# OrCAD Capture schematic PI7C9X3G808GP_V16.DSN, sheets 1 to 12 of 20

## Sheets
1 07_3V3_to_1V8&0.95V_LDO: size A; title: PI7C9X3G808GP reference circuit; rev: 1.6; note: 07_3V3_to_1V8&0.95V_LDO
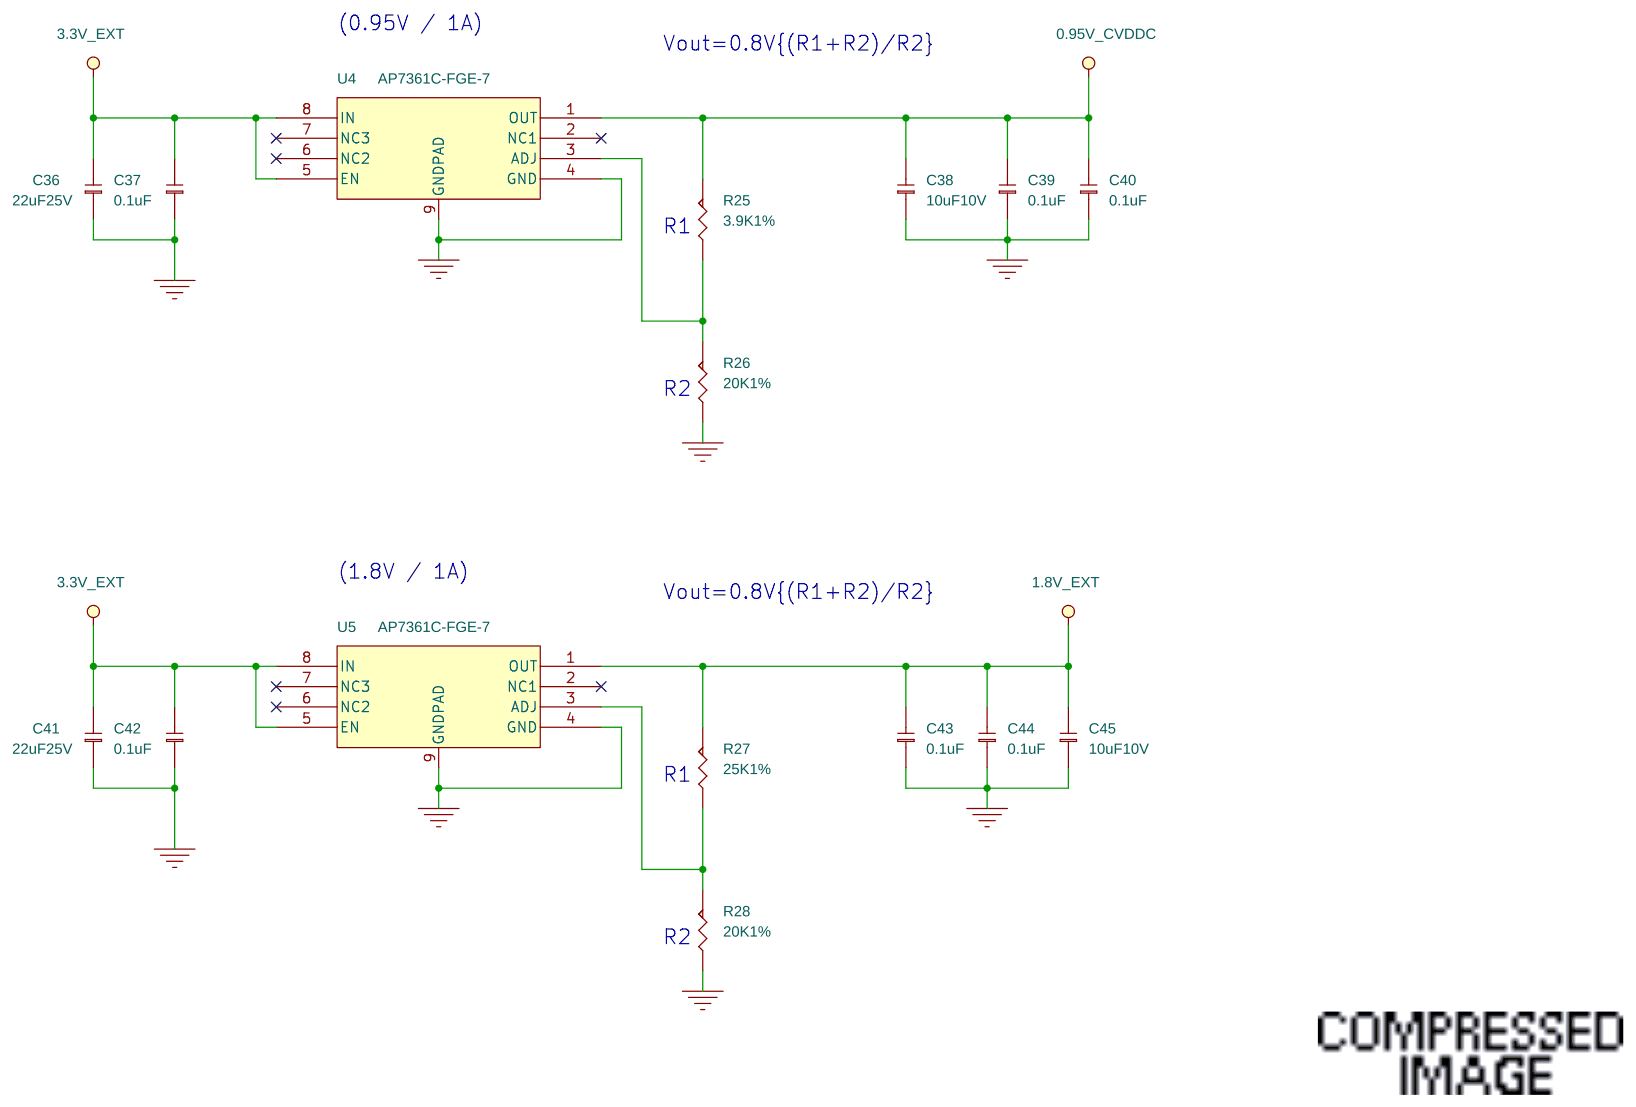
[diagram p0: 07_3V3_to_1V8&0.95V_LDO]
2 01_COVER SHEET: note: 01_COVER SHEET
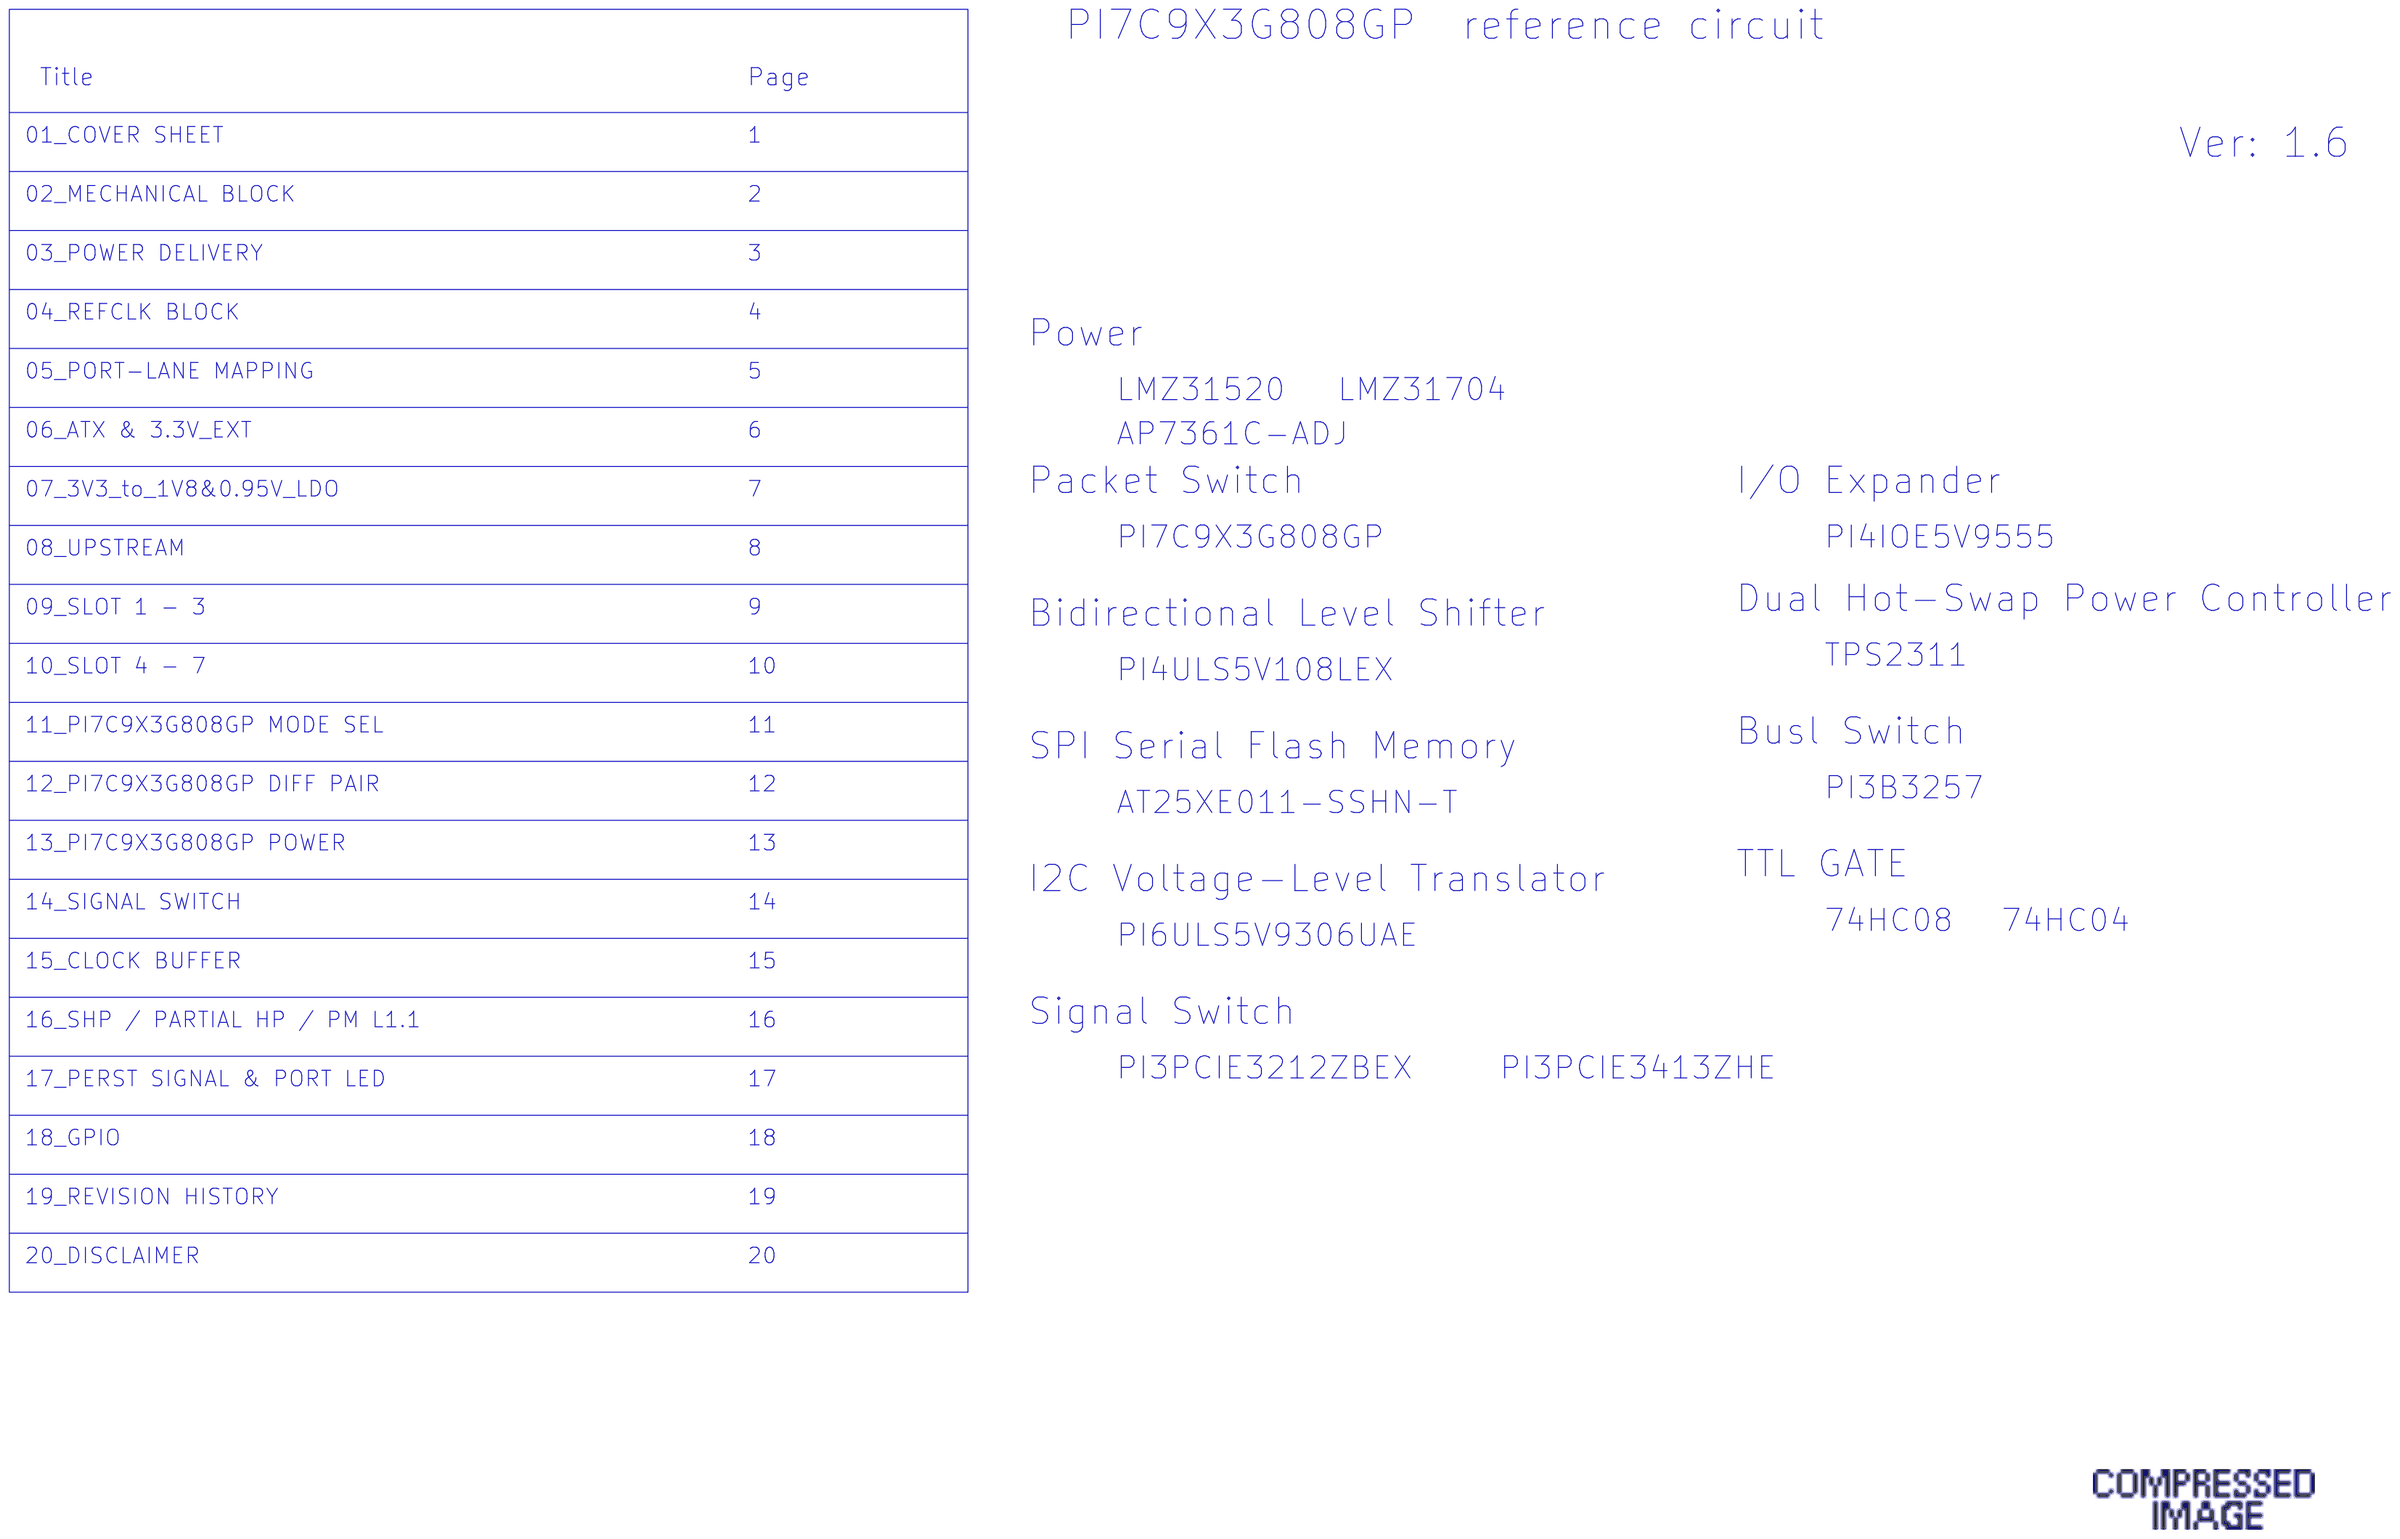
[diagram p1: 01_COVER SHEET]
3 02_MECHANICAL BLOCK: note: 02_MECHANICAL BLOCK
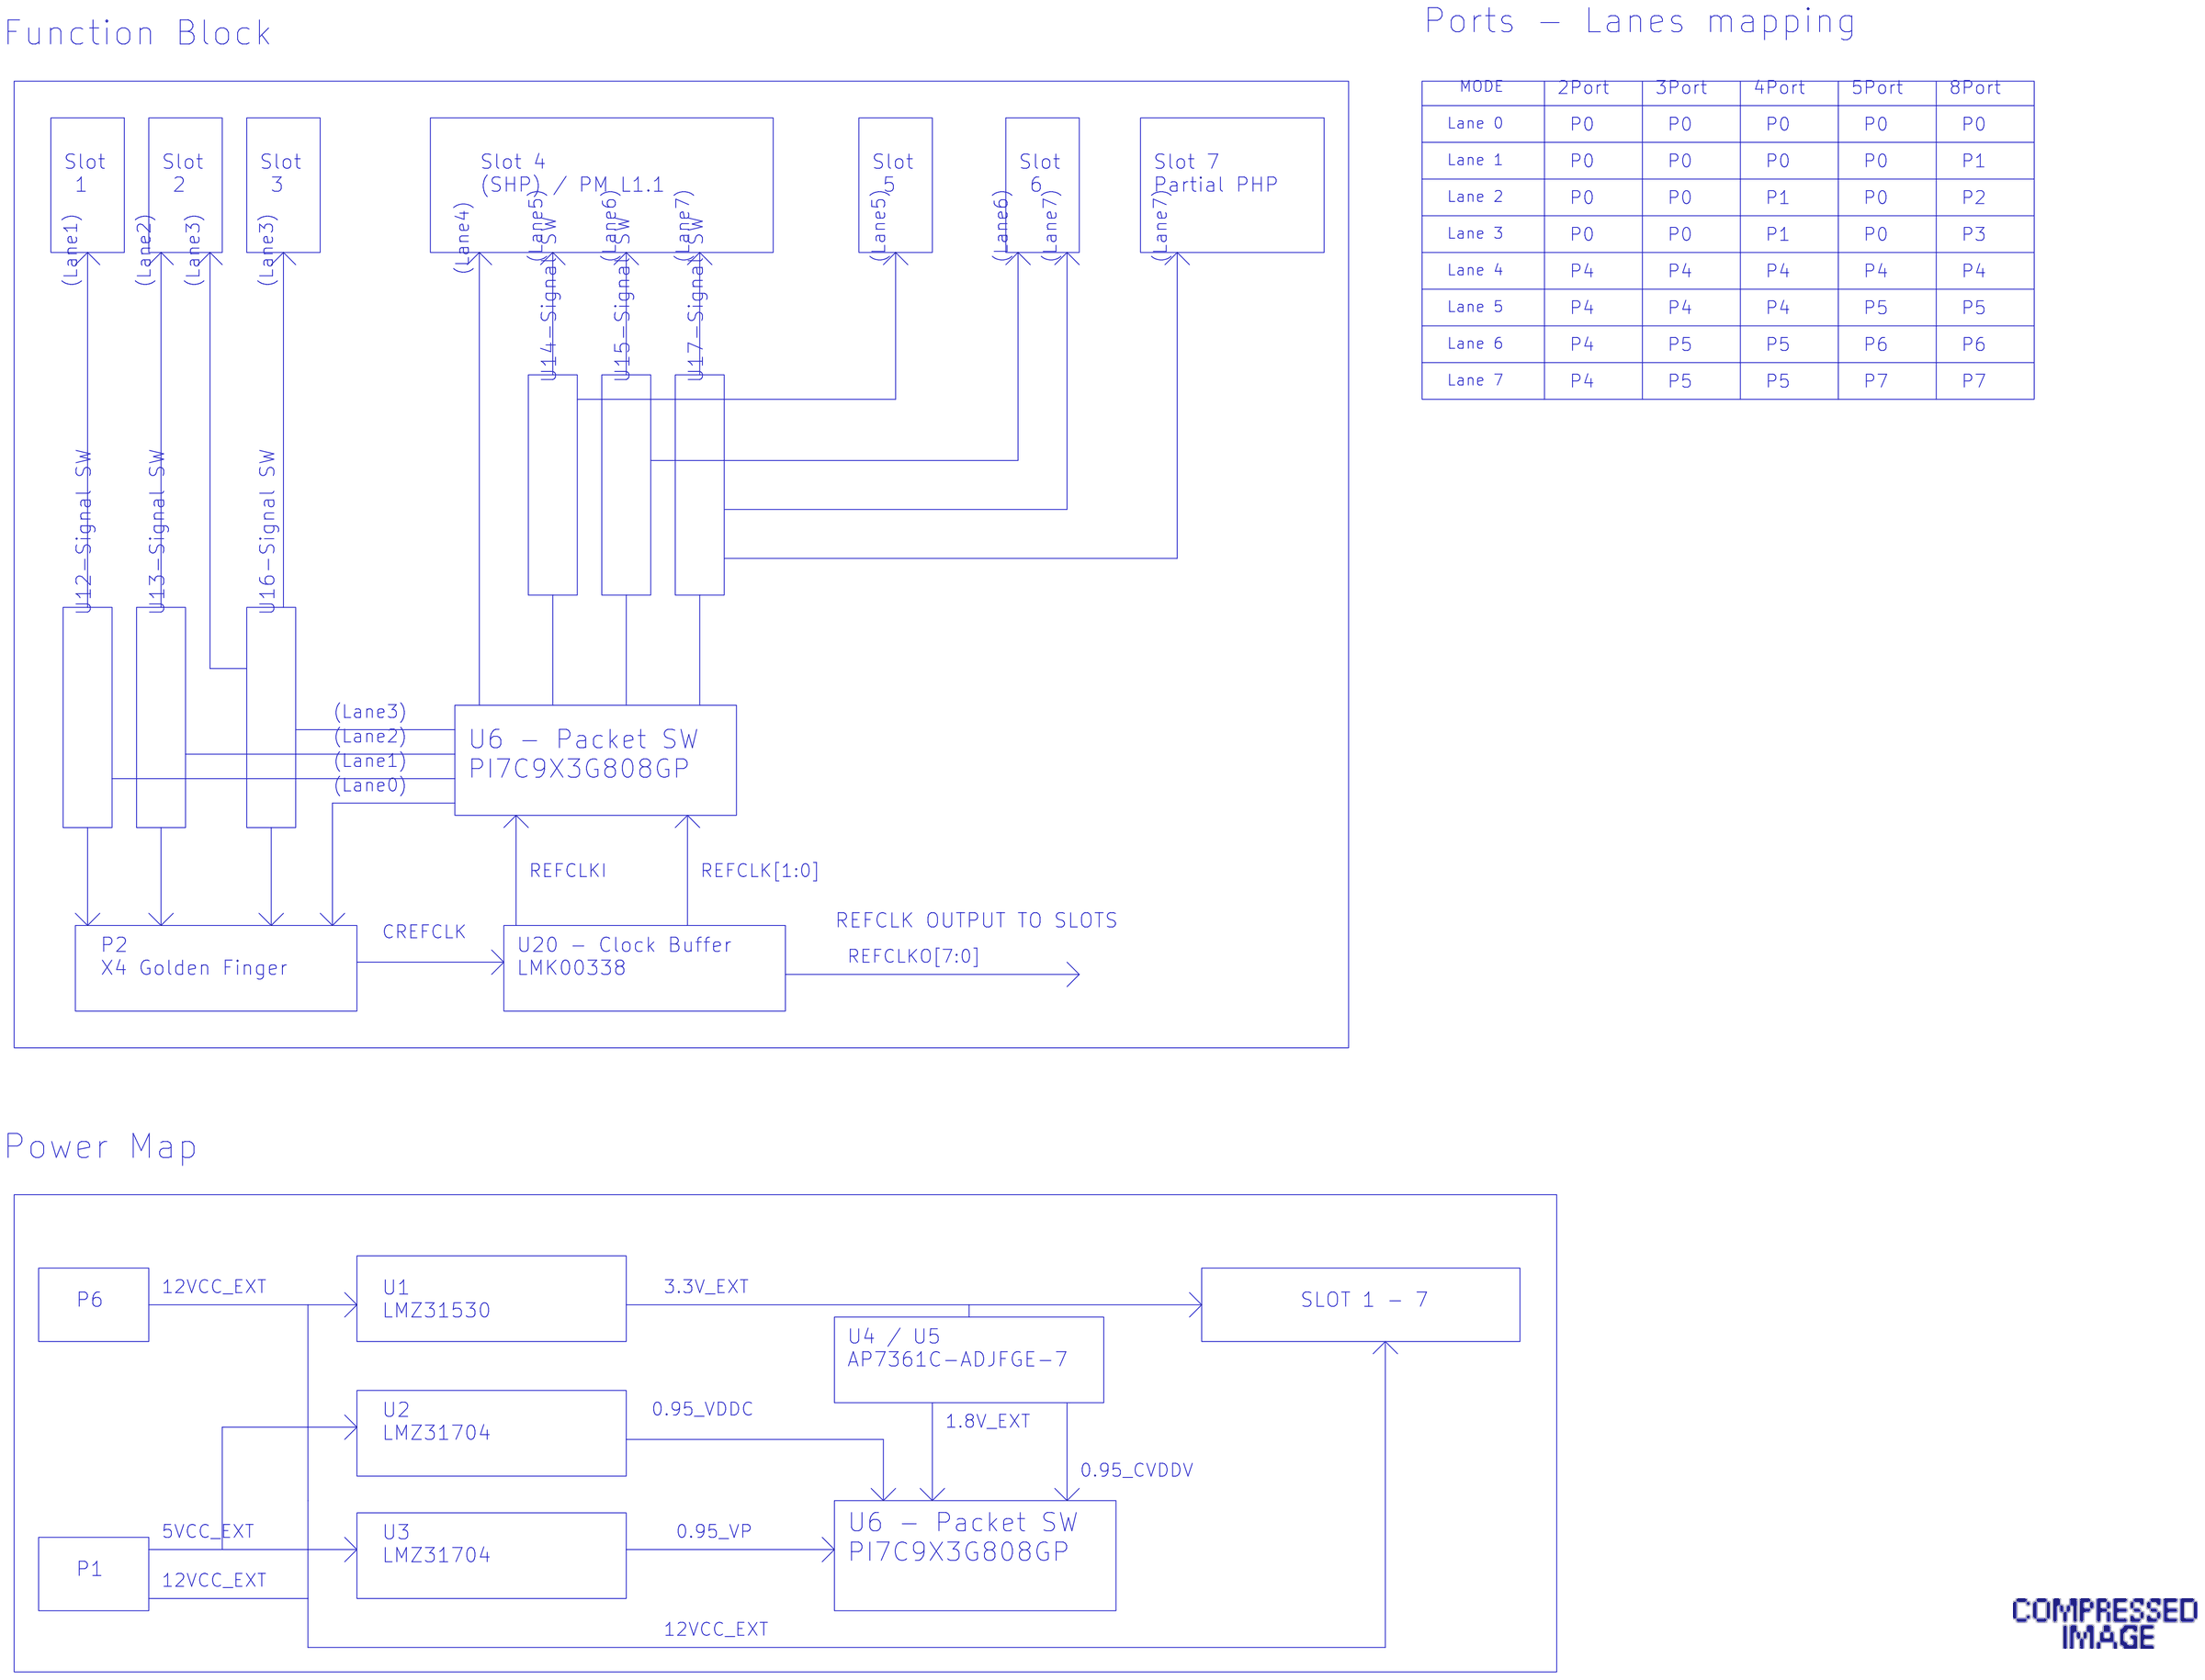
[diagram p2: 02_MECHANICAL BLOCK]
4 03_POWER DELIVERY: note: 03_POWER DELIVERY
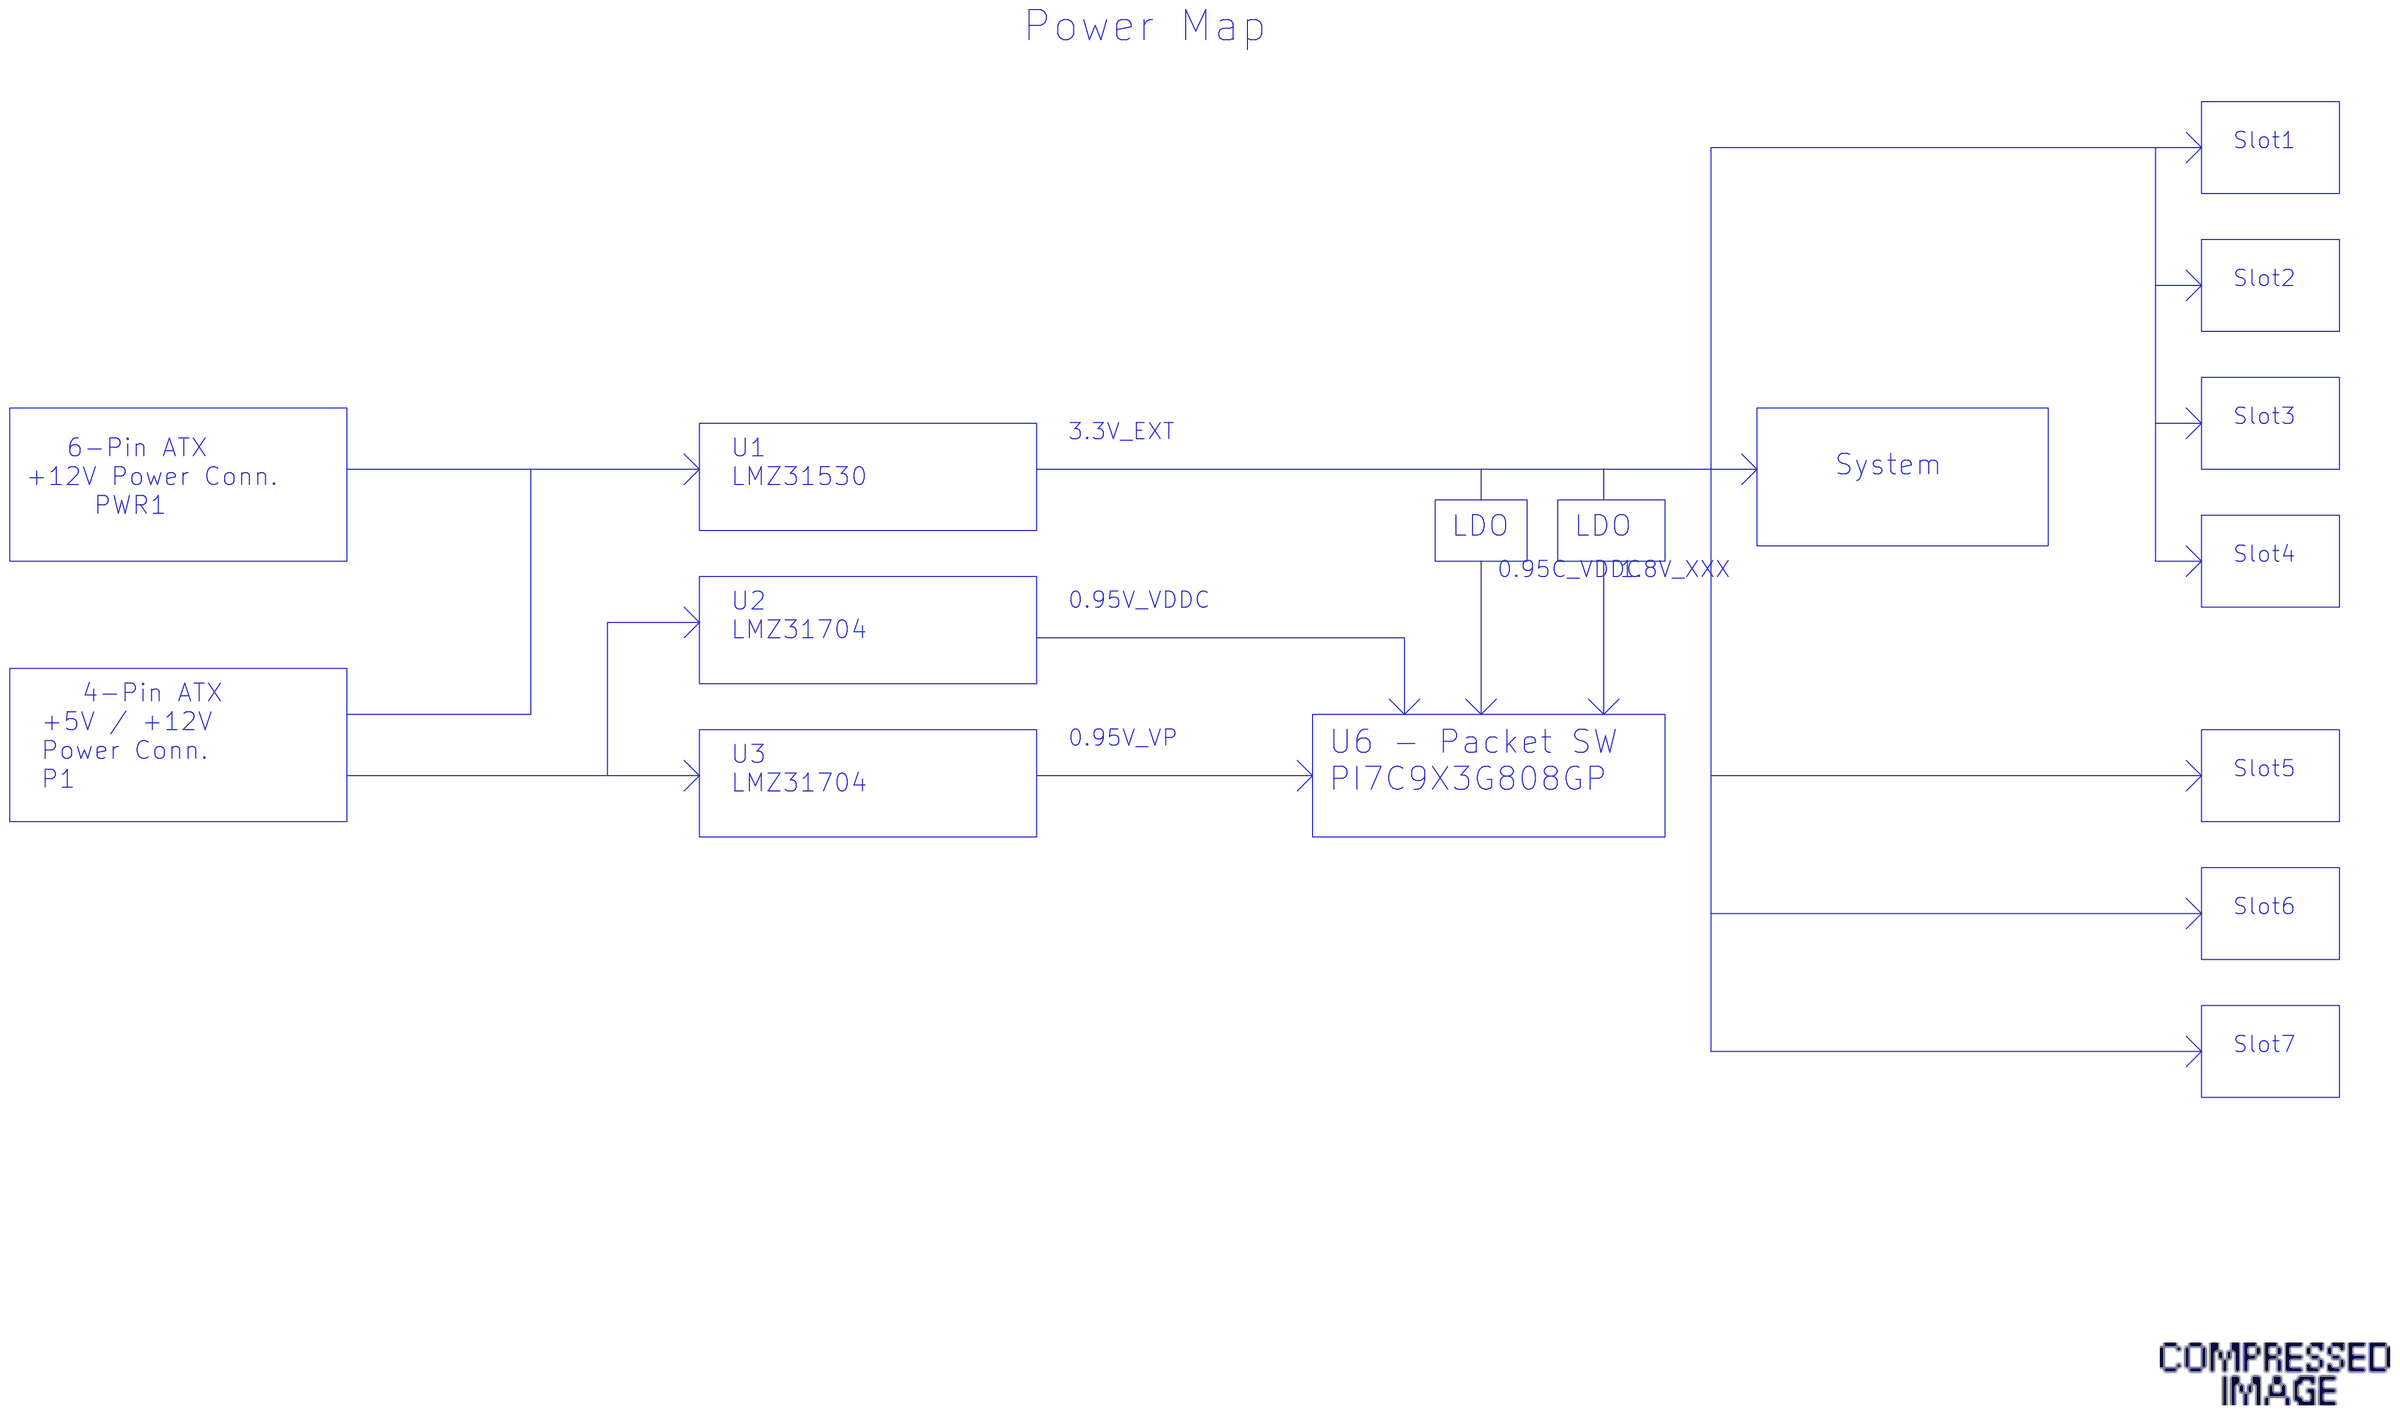
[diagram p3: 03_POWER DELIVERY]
5 04_REFCLK BLOCK: title: PI7C9X3G808GPA reference circuit; note: 04_REFCLK BLOCK
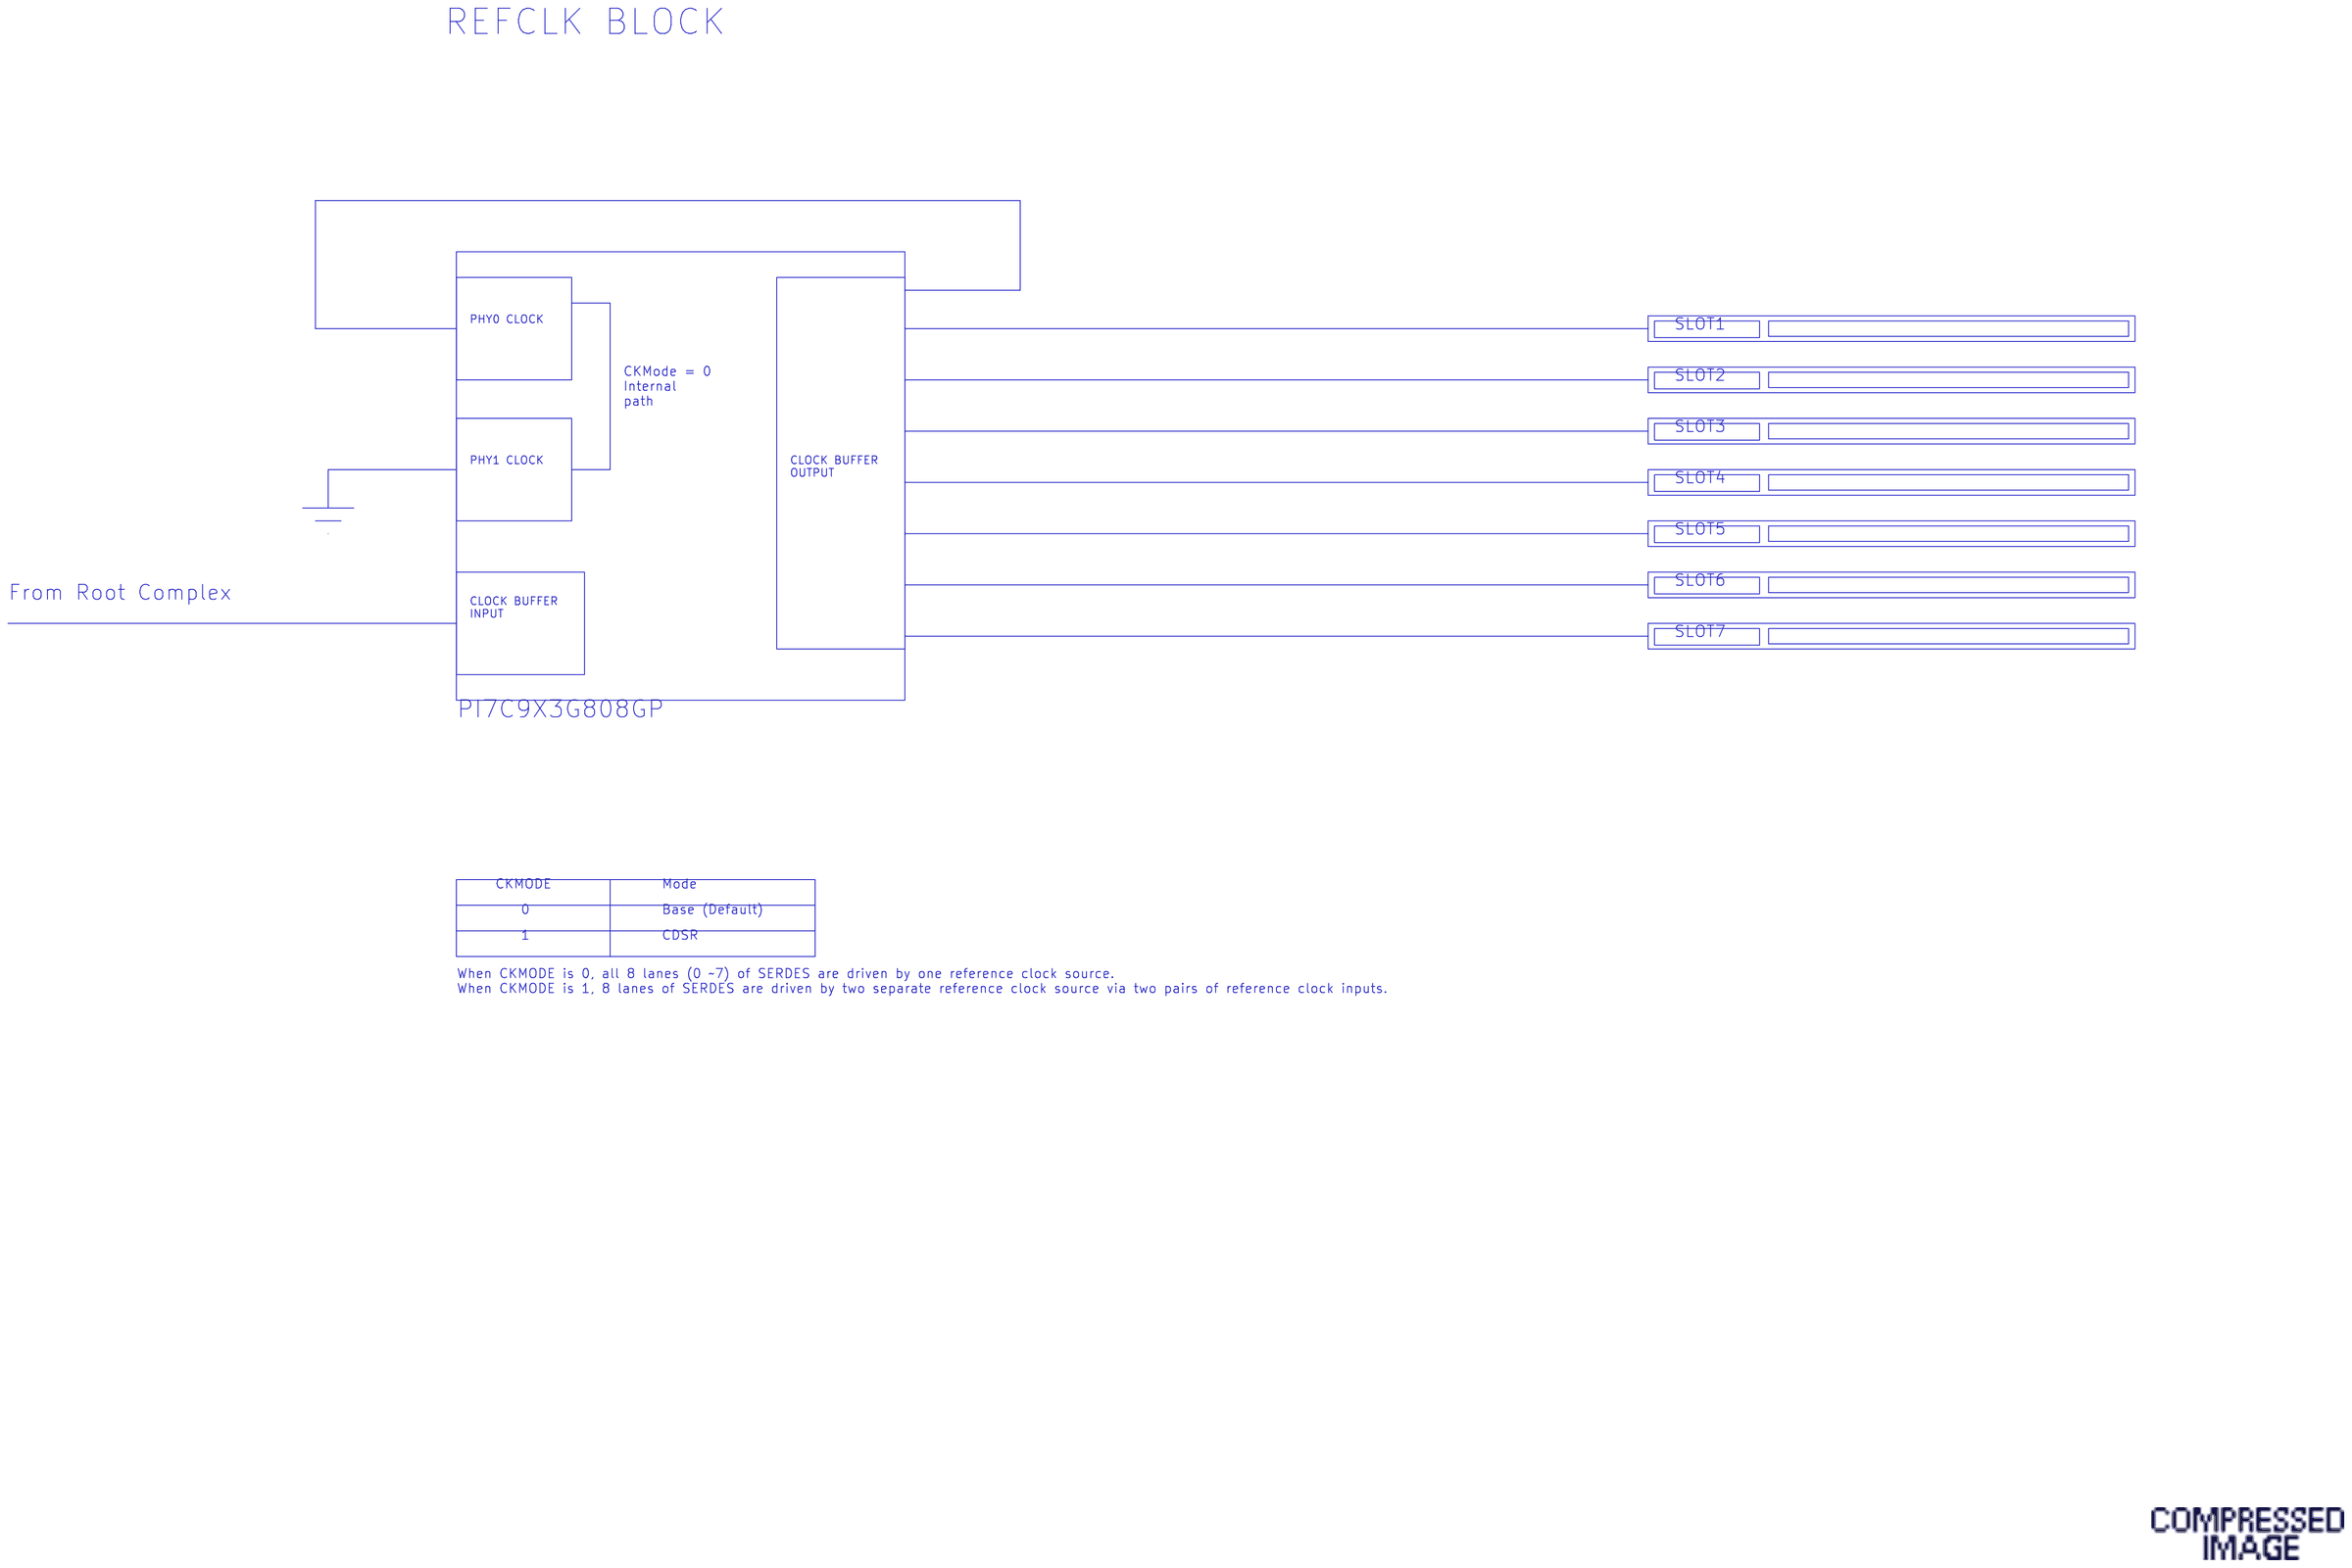
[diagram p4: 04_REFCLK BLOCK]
6 05_PORT-LANE MAPPING: note: 05_PORT-LANE MAPPING
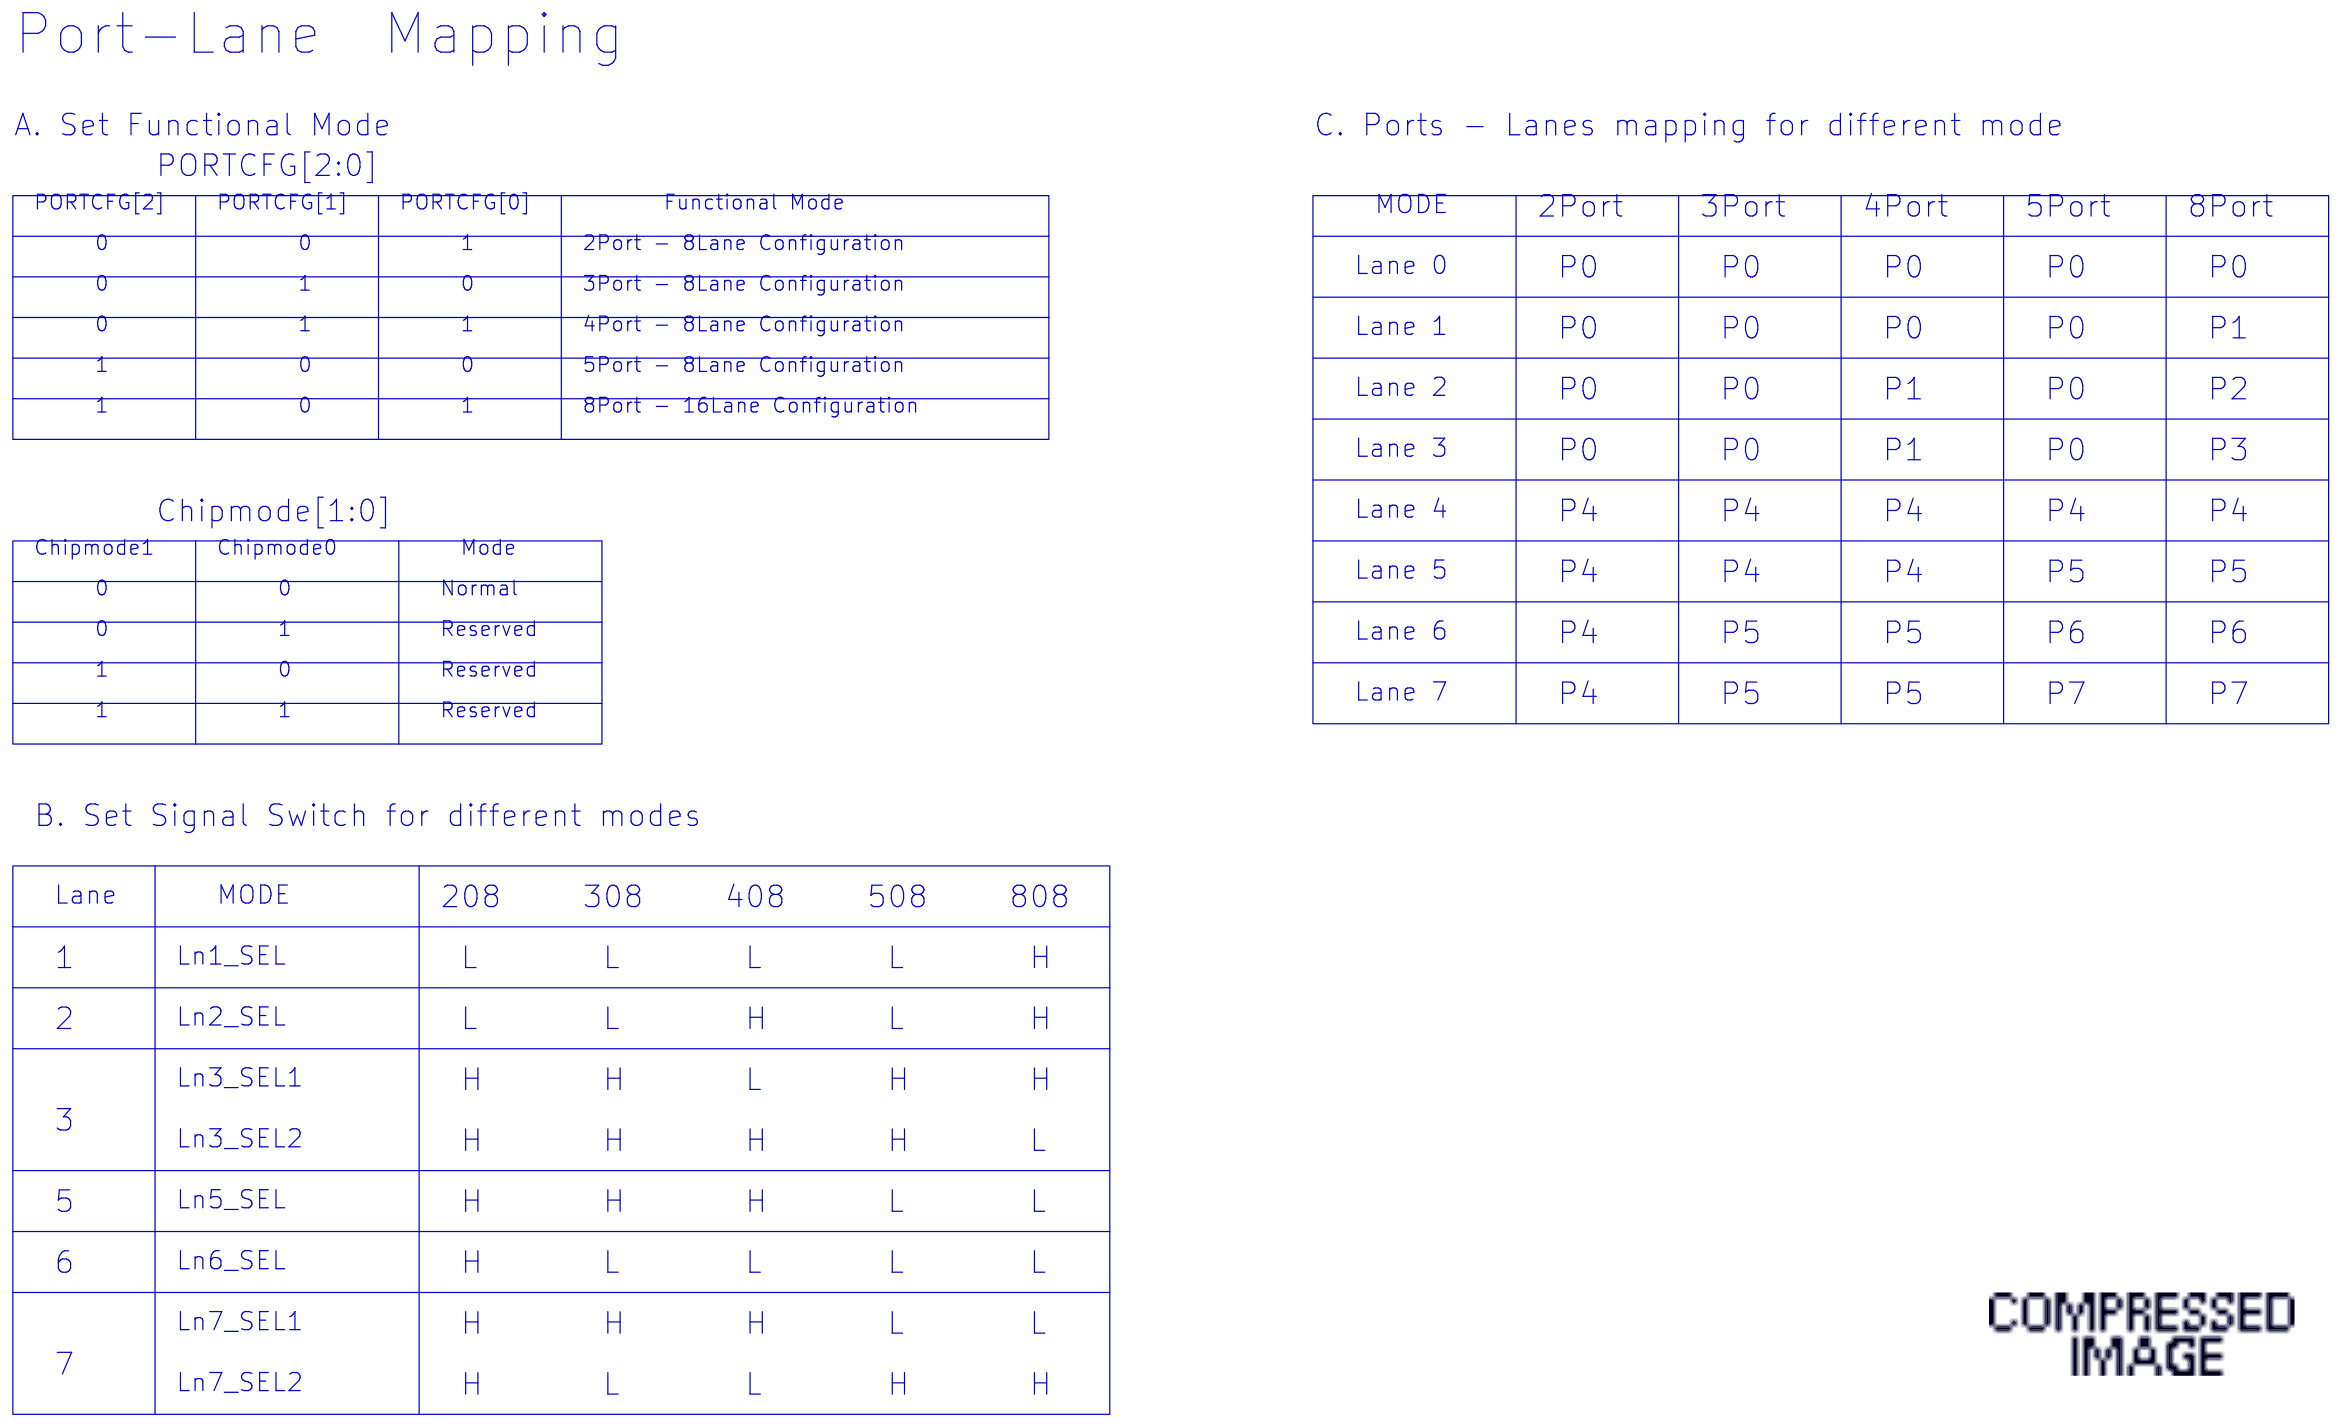
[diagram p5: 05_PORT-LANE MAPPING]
7 08_UPSTREAM: size Custom; note: 08_UPSTREAM
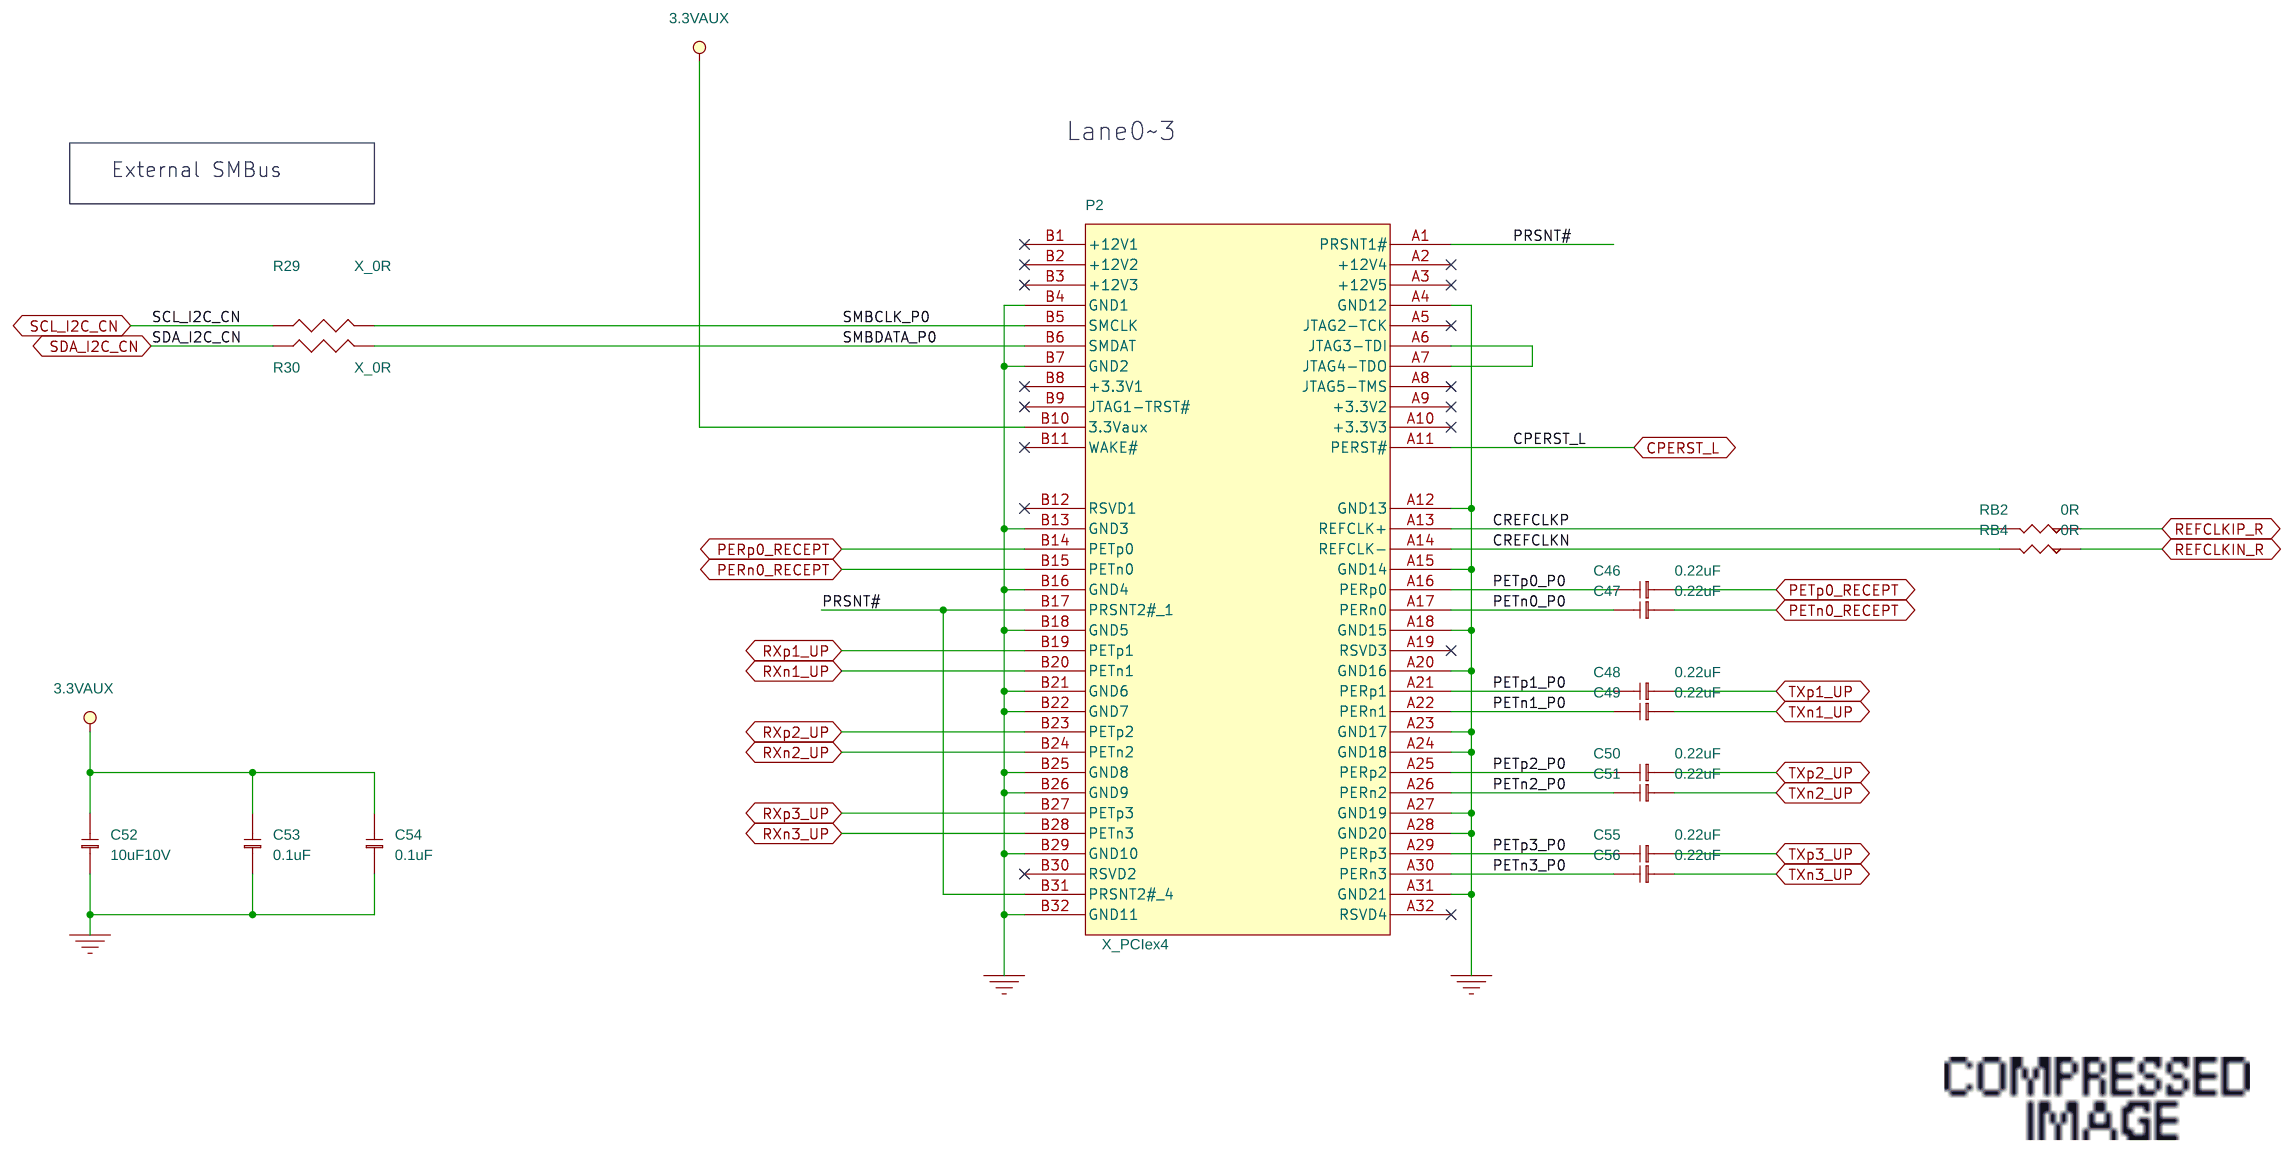
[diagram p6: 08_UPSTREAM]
8 10_SLOT 4 - 7: size Custom; note: 10_SLOT 4 - 7
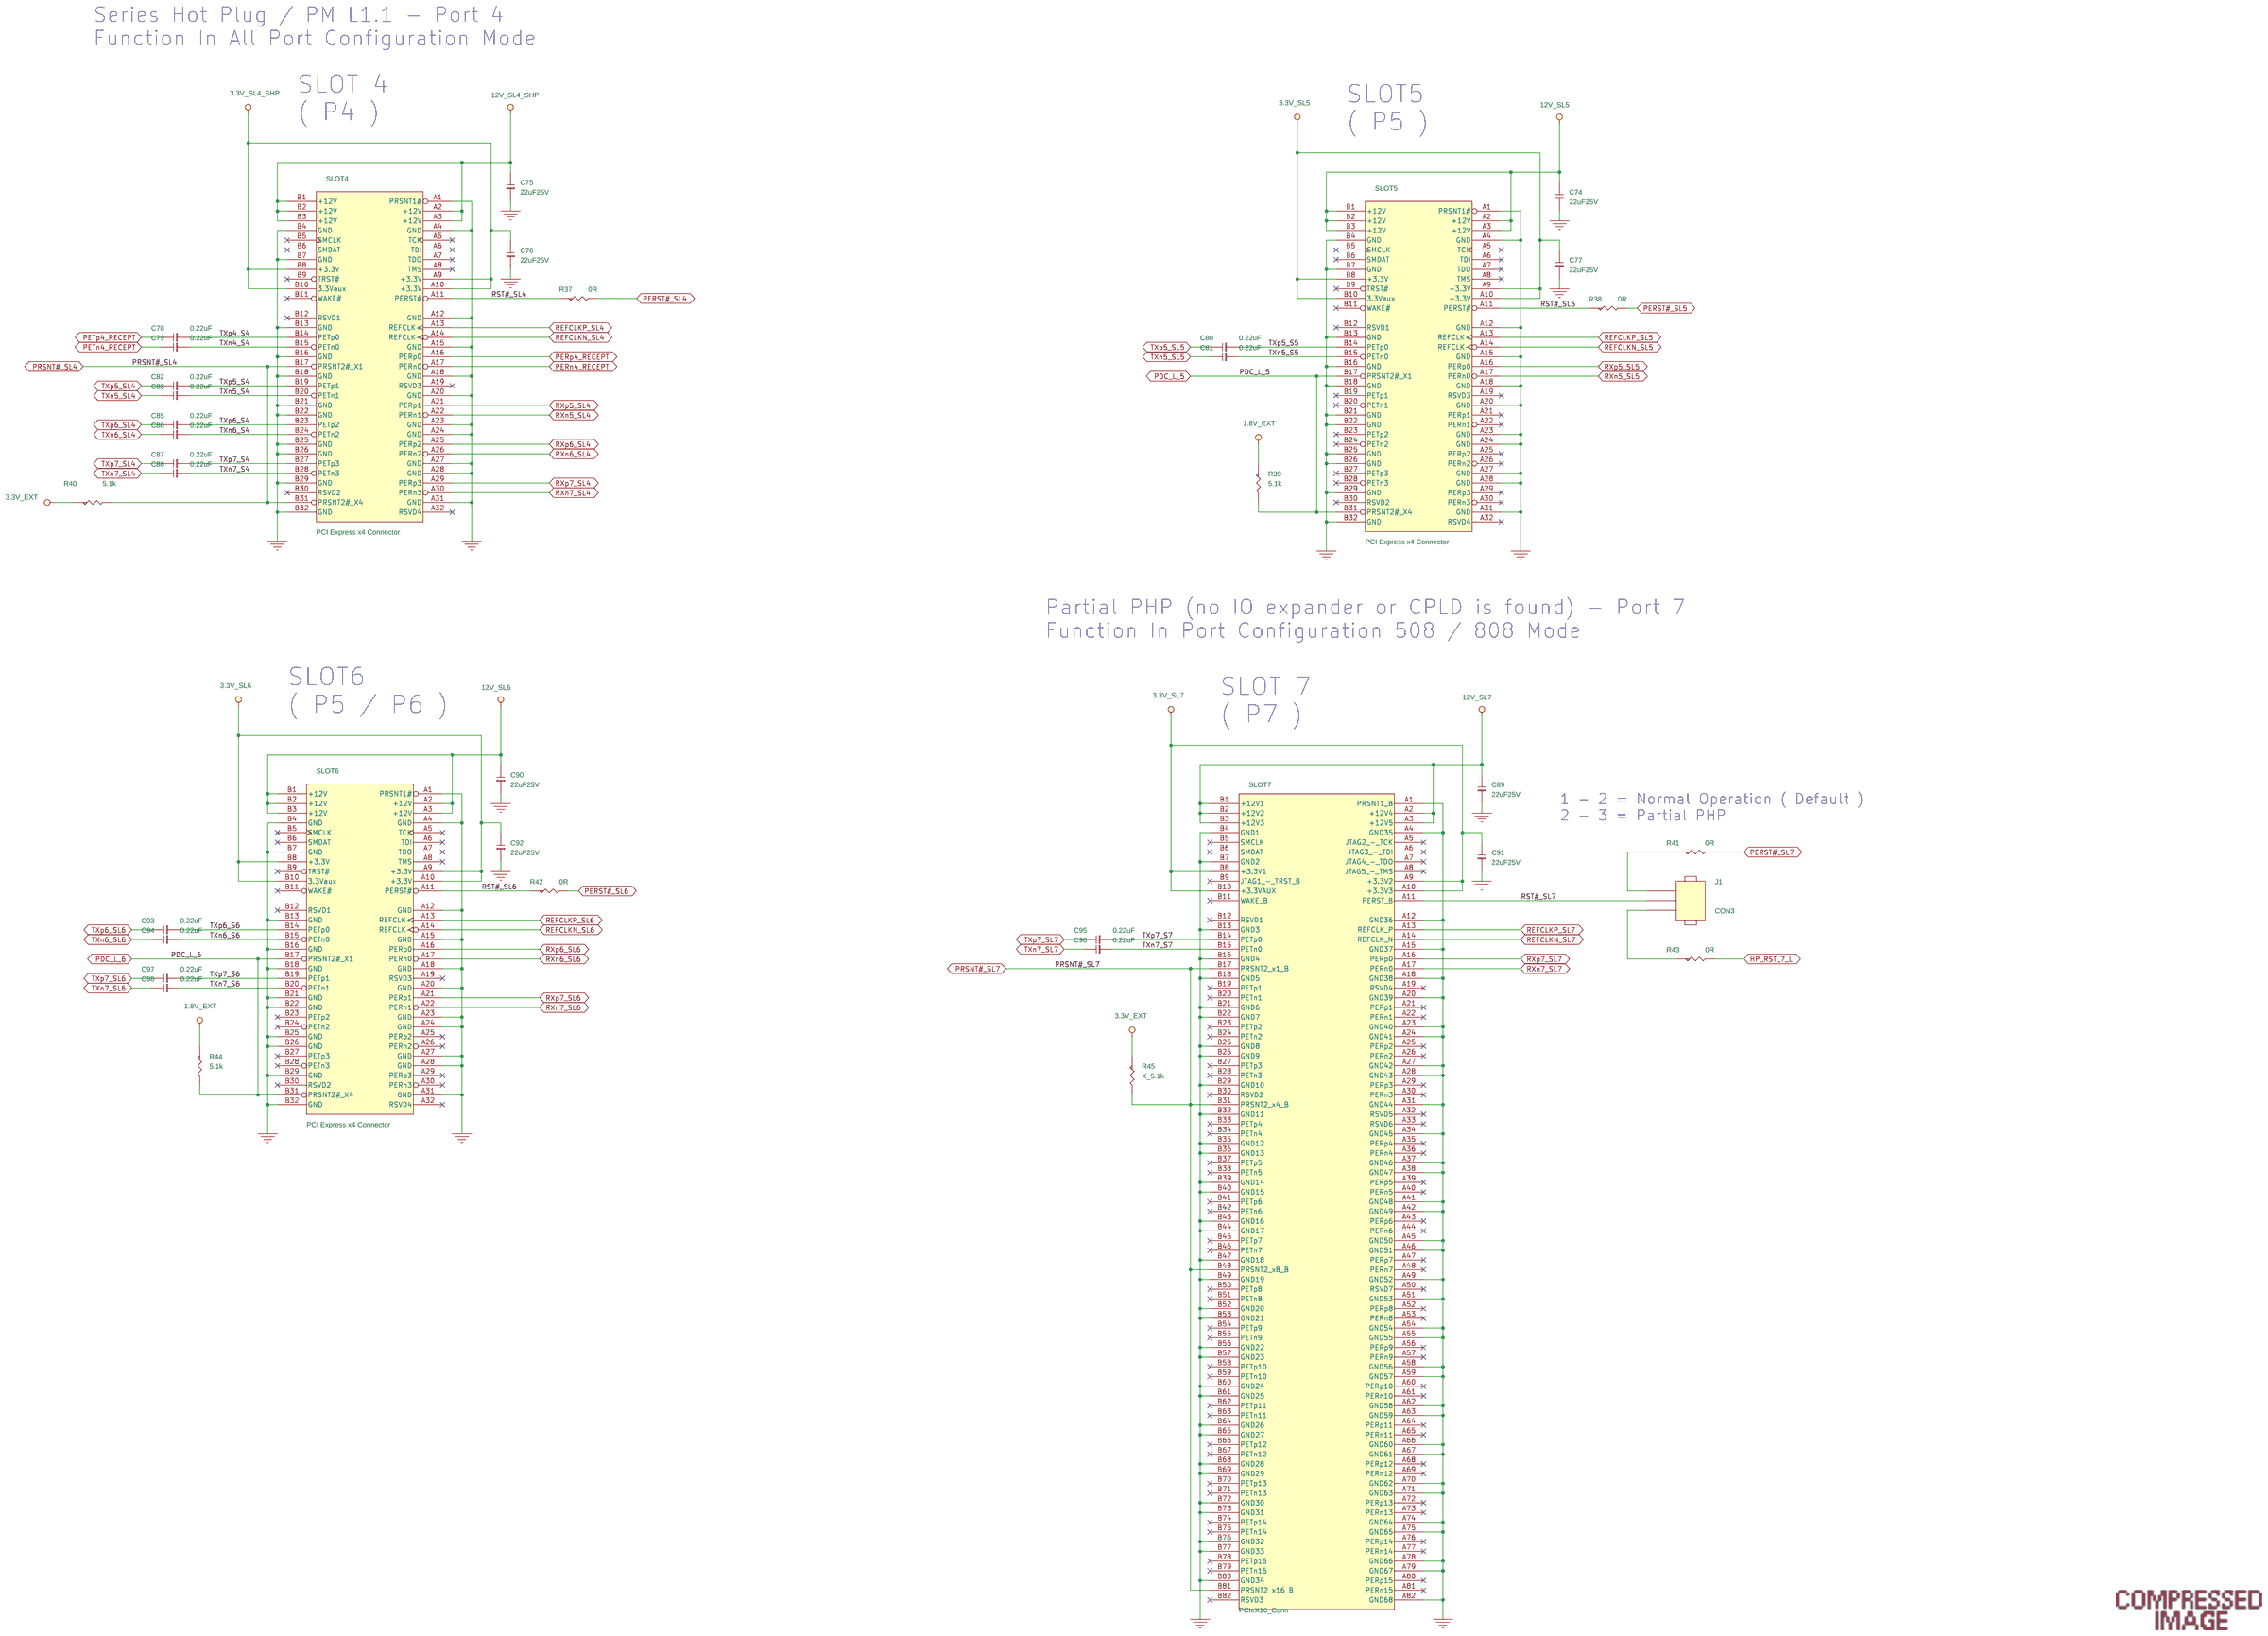
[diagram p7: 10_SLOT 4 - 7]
9 09_SLOT 1 - 3: size Custom; note: 09_SLOT 1 - 3
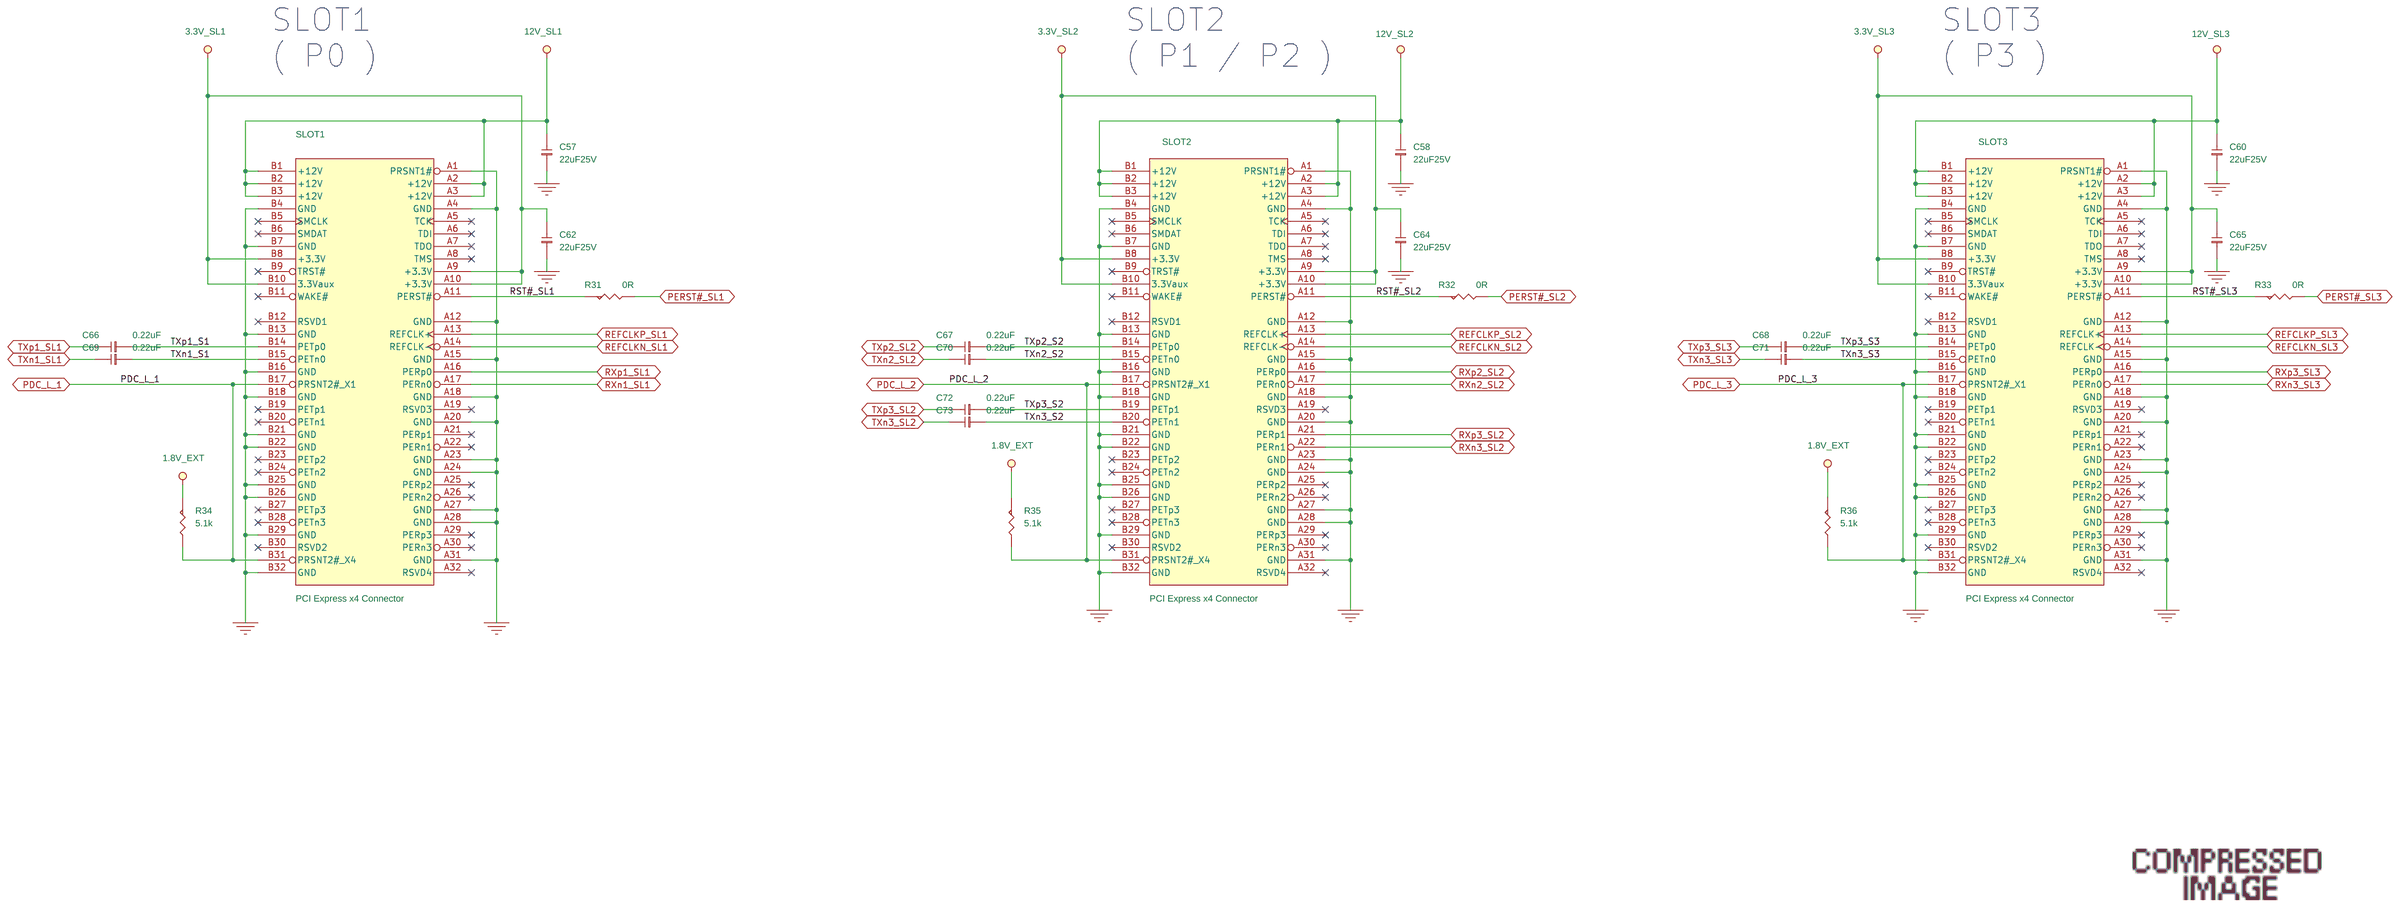
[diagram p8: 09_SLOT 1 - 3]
10 11_PI7C9X3G808GP MODE SEL: size Custom; note: 11_PI7C9X3G808GP MODE SEL
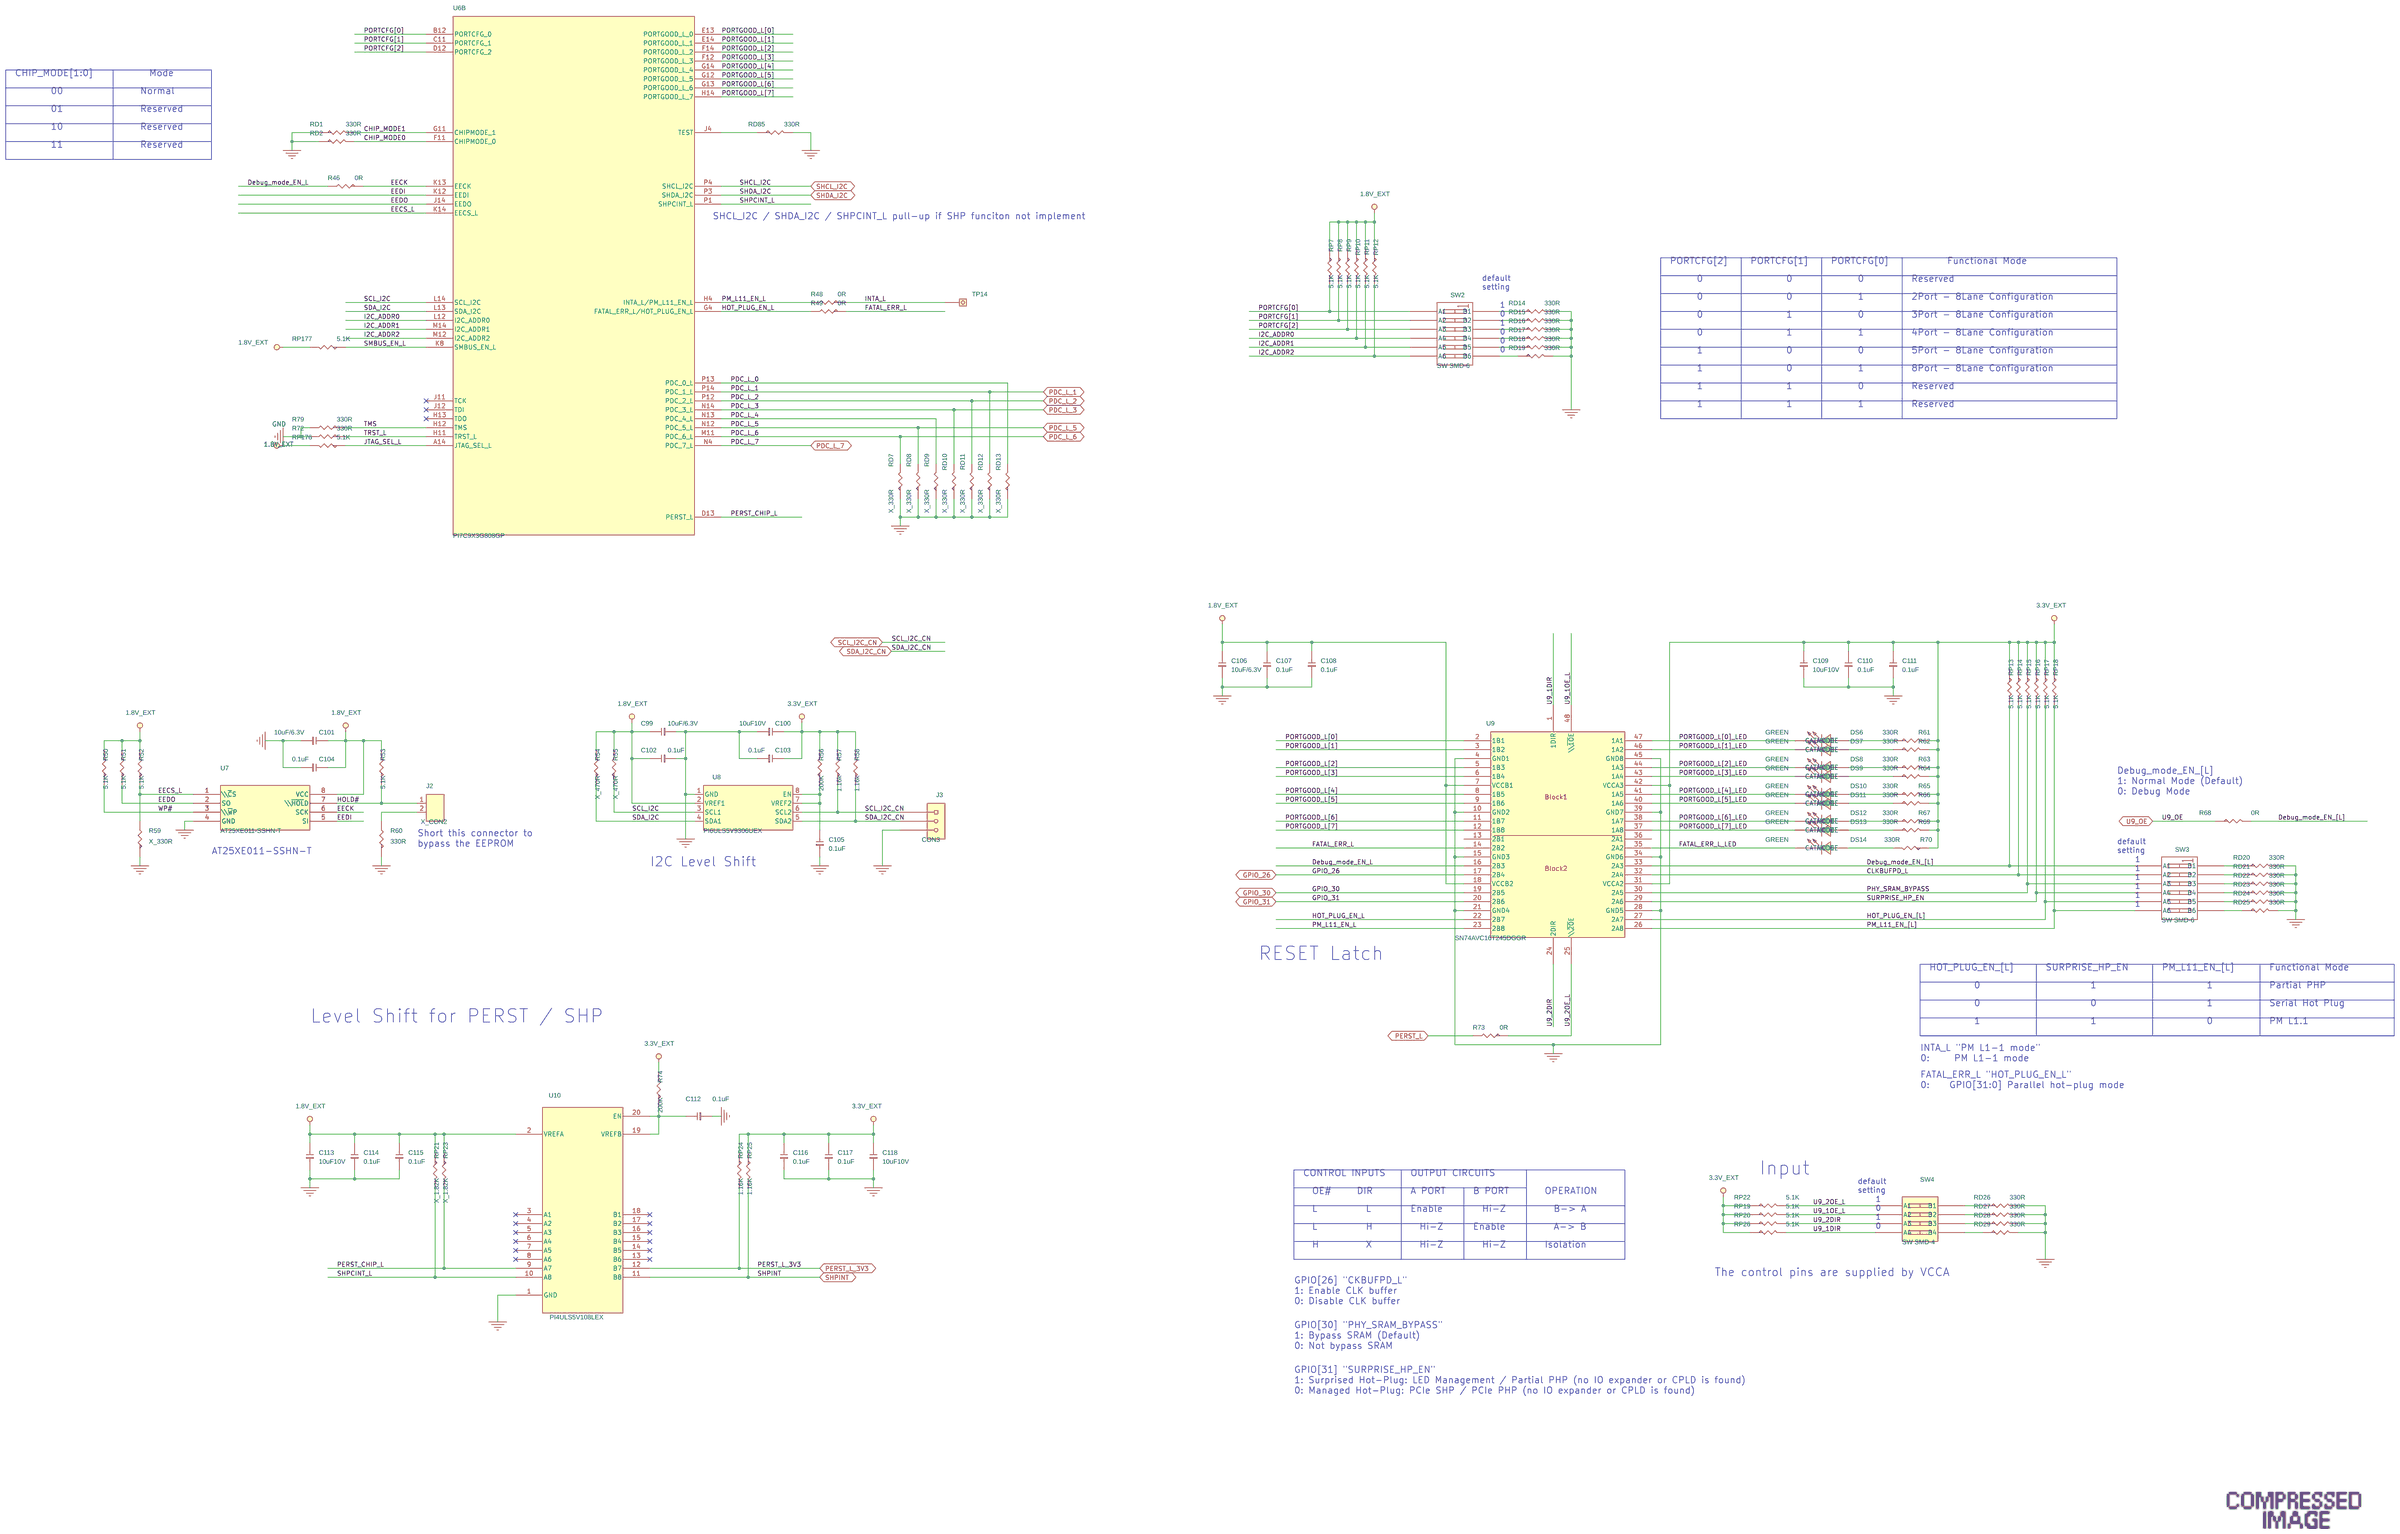
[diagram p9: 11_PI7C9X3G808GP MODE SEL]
11 12_PI7C9X3G808GP DIFF PAIR: size A; note: 12_PI7C9X3G808GP DIFF PAIR
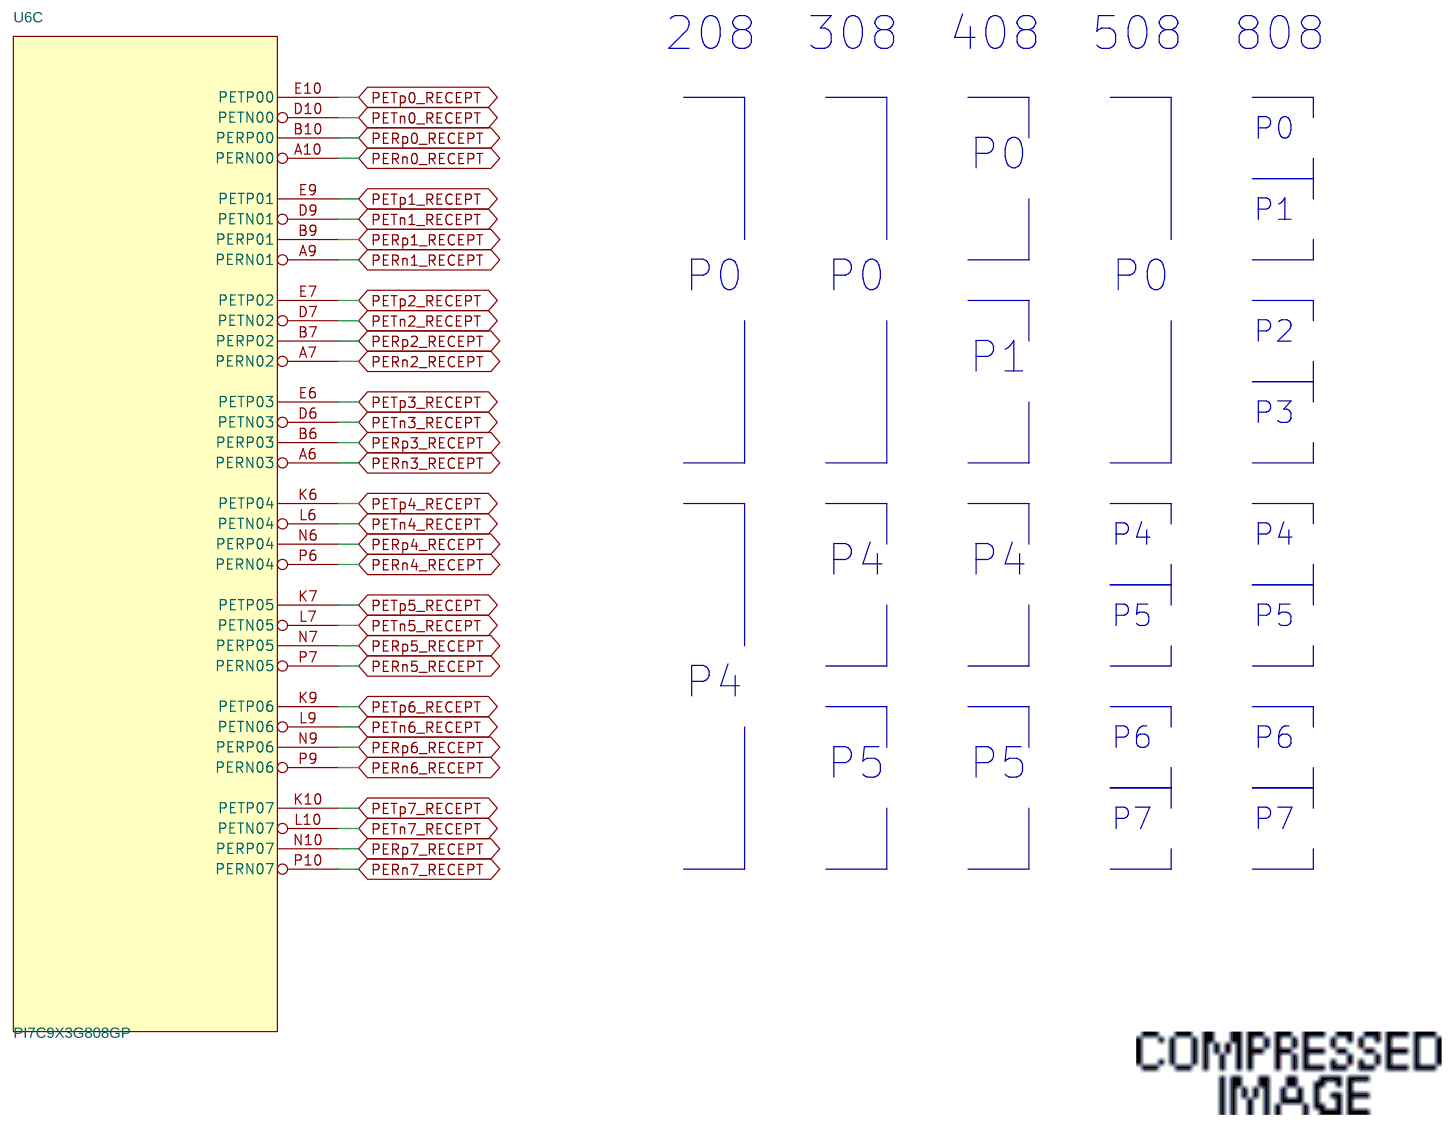
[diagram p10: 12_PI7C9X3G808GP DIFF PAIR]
12 13_PI7C9X3G808GP POWER: size Custom; note: 13_PI7C9X3G808GP POWER
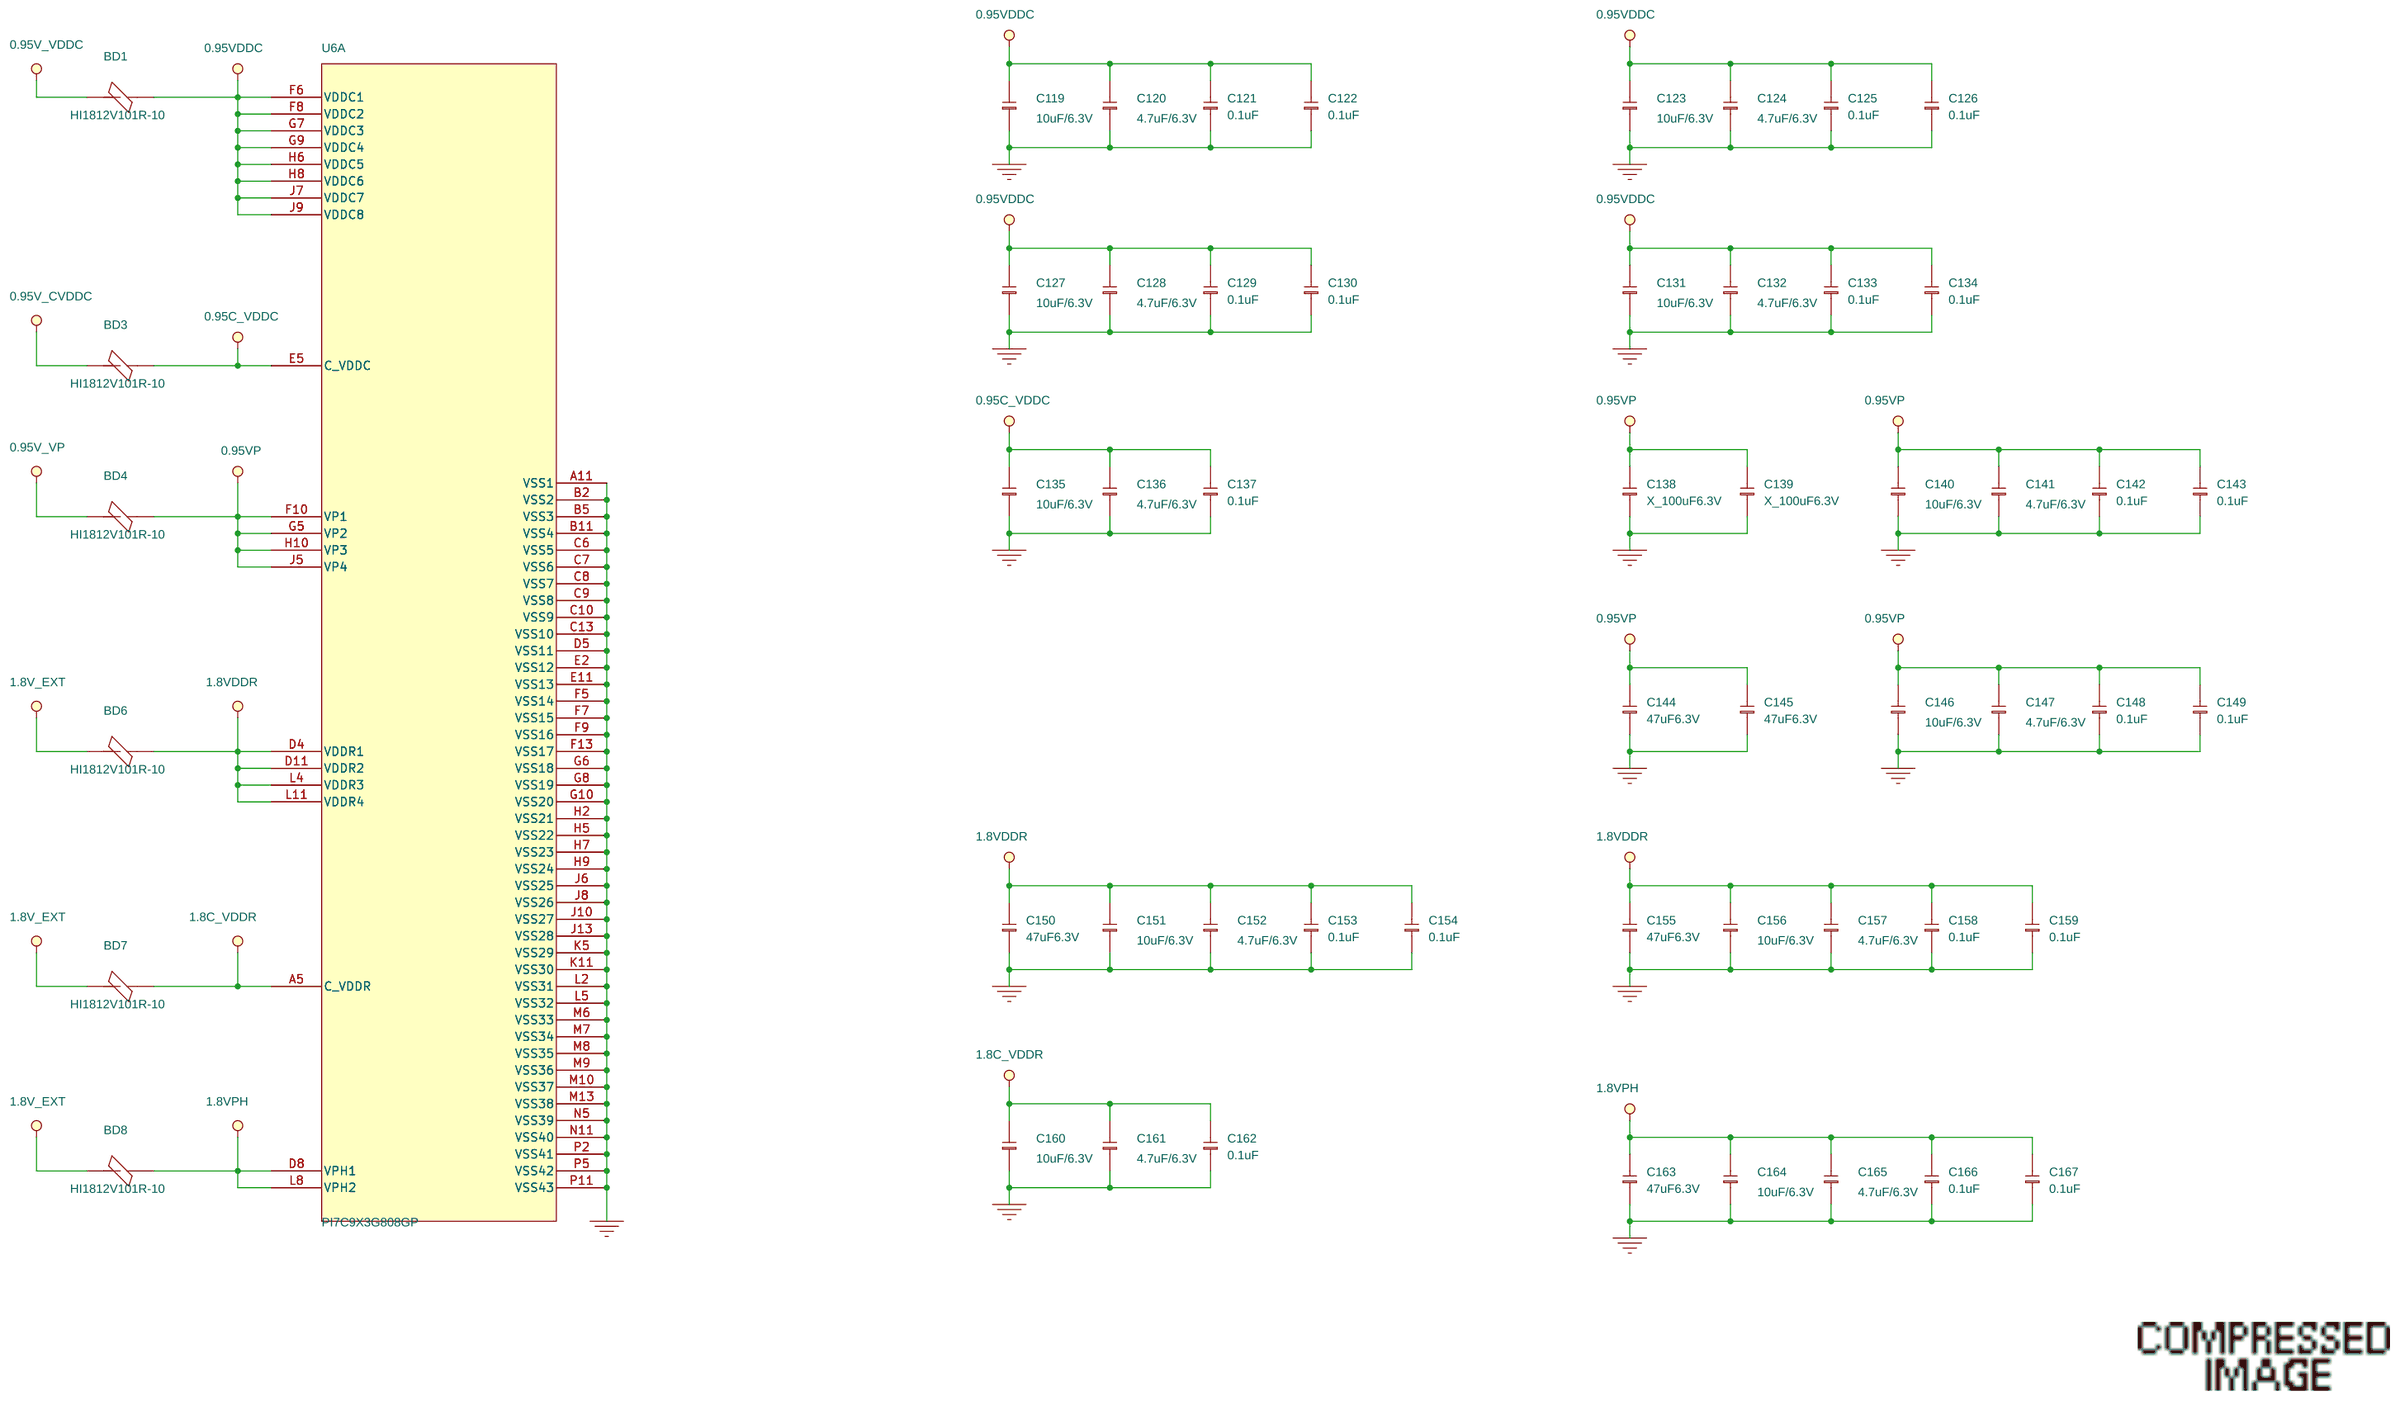
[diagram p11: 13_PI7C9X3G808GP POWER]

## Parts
sheet 07_3V3_to_1V8&0.95V_LDO
C36  22uF25V  [C1206]
C37  0.1uF  [C0402]
C38  10uF10V  [C0603]
C39  0.1uF  [C0402]
C40  0.1uF  [C0402]
C41  22uF25V  [C1206]
C42  0.1uF  [C0402]
C43  0.1uF  [C0402]
C44  0.1uF  [C0402]
C45  10uF10V  [C0603]
R25  3.9K1%  [R0402]
R26  20K1%  [R0402]
R27  25K1%  [R0402]
R28  20K1%  [R0402]
U4  AP7361C-FGE-7  [DFN8-0303-_65]
U5  AP7361C-FGE-7  [DFN8-0303-_65]
sheet 08_UPSTREAM
C46  0.22uF  [C0201]
C47  0.22uF  [C0201]
C48  0.22uF  [C0201]
C49  0.22uF  [C0201]
C50  0.22uF  [C0201]
C51  0.22uF  [C0201]
C52  10uF10V  [C0603]
C53  0.1uF  [C0402]
C54  0.1uF  [C0402]
C55  0.22uF  [C0201]
C56  0.22uF  [C0201]
P2  X_PCIex4  [PCI_EXPRESS_X4]
R29  X_0R  [R0402]
R30  X_0R  [R0402]
RB2  0R  [R0402]
RB4  0R  [R0402]
sheet 09_SLOT 1 - 3
C57  22uF25V  [C1206]
C58  22uF25V  [C1206]
C60  22uF25V  [C1206]
C62  22uF25V  [C1206]
C64  22uF25V  [C1206]
C65  22uF25V  [C1206]
C66  0.22uF  [C0402]
C67  0.22uF  [C0402]
C68  0.22uF  [C0402]
C69  0.22uF  [C0402]
C70  0.22uF  [C0402]
C71  0.22uF  [C0402]
C72  0.22uF  [C0402]
C73  0.22uF  [C0402]
R31  0R  [R0402]
R32  0R  [R0402]
R33  0R  [R0402]
R34  5.1k  [R0402]
R35  5.1k  [R0402]
R36  5.1k  [R0402]
SLOT1  PCI Express x4 Connector  [PCI_EXP_SLOT_X4]
SLOT2  PCI Express x4 Connector  [PCI_EXP_SLOT_X4]
SLOT3  PCI Express x4 Connector  [PCI_EXP_SLOT_X4]
sheet 10_SLOT 4 - 7
C74  22uF25V  [C1206]
C75  22uF25V  [C1206]
C76  22uF25V  [C1206]
C77  22uF25V  [C1206]
C78  0.22uF  [C0402]
C79  0.22uF  [C0402]
C80  0.22uF  [C0402]
C81  0.22uF  [C0402]
C82  0.22uF  [C0402]
C83  0.22uF  [C0402]
C85  0.22uF  [C0402]
C86  0.22uF  [C0402]
C87  0.22uF  [C0402]
C88  0.22uF  [C0402]
C89  22uF25V  [C1206]
C90  22uF25V  [C1206]
C91  22uF25V  [C1206]
C92  22uF25V  [C1206]
C93  0.22uF  [C0402]
C94  0.22uF  [C0402]
C95  0.22uF  [C0402]
C96  0.22uF  [C0402]
C97  0.22uF  [C0402]
C98  0.22uF  [C0402]
J1  CON3  [HEAD1X3_2_54MM]
R37  0R  [R0402]
R38  0R  [R0402]
R39  5.1k  [R0402]
R40  5.1k  [R0402]
R41  0R  [R0402]
R42  0R  [R0402]
R43  0R  [R0402]
R44  5.1k  [R0402]
R45  X_5.1k  [R0402]
SLOT4  PCI Express x4 Connector  [PCI_EXP_SLOT_X4]
SLOT5  PCI Express x4 Connector  [PCI_EXP_SLOT_X4]
SLOT6  PCI Express x4 Connector  [PCI_EXP_SLOT_X4]
SLOT7  PCIeX16_Conn  [pci-exp-16x]
sheet 11_PI7C9X3G808GP MODE SEL
C99  10uF/6.3V  [C0402]
C100  10uF10V  [C0603]
C101  10uF/6.3V  [C0402]
C102  0.1uF  [C0402]
C103  0.1uF  [C0402]
C104  0.1uF  [C0402]
C105  0.1uF  [C0402]
C106  10uF/6.3V  [C0402]
C107  0.1uF  [C0402]
C108  0.1uF  [C0402]
C109  10uF10V  [C0603]
C110  0.1uF  [C0402]
C111  0.1uF  [C0402]
C112  0.1uF  [C0402]
C113  10uF10V  [C0603]
C114  0.1uF  [C0402]
C115  0.1uF  [C0402]
C116  0.1uF  [C0402]
C117  0.1uF  [C0402]
C118  10uF10V  [C0603]
DS6  GREEN  [LED-0805]
DS7  GREEN  [LED-0805]
DS8  GREEN  [LED-0805]
DS9  GREEN  [LED-0805]
DS10  GREEN  [LED-0805]
DS11  GREEN  [LED-0805]
DS12  GREEN  [LED-0805]
DS13  GREEN  [LED-0805]
DS14  GREEN  [LED-0805]
J2  X_CON2  [HEAD1X2_2_54MM]
J3  CON3  [HEAD1X3_2_54MM]
R46  0R  [R0402]
R48  0R  [R0402]
R49  0R  [R0402]
R50  5.1K  [R0402]
R51  5.1K  [R0402]
R52  5.1K  [R0402]
R53  5.1K  [R0402]
R54  X_470R  [R0402]
R55  X_470R  [R0402]
R56  200K  [R0402]
R57  1.16k  [R0402]
R58  1.16k  [R0402]
R59  X_330R  [R0402]
R60  330R  [R0402]
R61  330R  [R0402]
R62  330R  [R0402]
R63  330R  [R0402]
R64  330R  [R0402]
R65  330R  [R0402]
R66  330R  [R0402]
R67  330R  [R0402]
R68  0R  [R0402]
R69  330R  [R0402]
R70  330R  [R0402]
R72  330R  [R0402]
R73  0R  [R0402]
R74  200K  [R0402]
R79  330R  [R0402]
RD1  330R  [R0402]
RD2  330R  [R0402]
RD7  X_330R  [R0402]
RD8  X_330R  [R0402]
RD9  X_330R  [R0402]
RD10  X_330R  [R0402]
RD11  X_330R  [R0402]
RD12  X_330R  [R0402]
RD13  X_330R  [R0402]
RD14  330R  [R0402]
RD15  330R  [R0402]
RD16  330R  [R0402]
RD17  330R  [R0402]
RD18  330R  [R0402]
RD19  330R  [R0402]
RD20  330R  [R0402]
RD21  330R  [R0402]
RD22  330R  [R0402]
RD23  330R  [R0402]
RD24  330R  [R0402]
RD25  330R  [R0402]
RD26  330R  [R0402]
RD27  330R  [R0402]
RD28  330R  [R0402]
RD29  330R  [R0402]
RD85  330R  [R0402]
RP7  5.1K  [R0402]
RP8  5.1K  [R0402]
RP9  5.1K  [R0402]
RP10  5.1K  [R0402]
RP11  5.1K  [R0402]
RP12  5.1K  [R0402]
RP13  5.1K  [R0402]
RP14  5.1K  [R0402]
RP15  5.1K  [R0402]
RP16  5.1K  [R0402]
RP17  5.1K  [R0402]
RP18  5.1K  [R0402]
RP19  5.1K  [R0402]
RP20  5.1K  [R0402]
RP21  X_1.82K  [R0402]
RP22  5.1K  [R0402]
RP23  X_1.82K  [R0402]
RP24  1.16K  [R0402]
RP25  1.16K  [R0402]
RP26  5.1K  [R0402]
RP176  5.1K  [R0402]
RP177  5.1K  [R0402]
SW2  SW SMD-6  [CT2186LPST]
SW3  SW SMD-6  [CT2186LPST]
SW4  SW SMD-4  [CT2184LPST]
TP14  X_TESTPOINT  [TESTPIN25]
U7  AT25XE011-SSHN-T  [so8-8-1_27-pad]
U8  PI6ULS5V9306UEX  [MSOP-8L]
U9  SN74AVC16T245DGGR  [48-TSSOP]
U10  PI4ULS5V108LEX  [tssop20-6_5-_65]
sheet 13_PI7C9X3G808GP POWER
BD1  HI1812V101R-10  [L1812]
BD3  HI1812V101R-10  [L1812]
BD4  HI1812V101R-10  [L1812]
BD6  HI1812V101R-10  [L1812]
BD7  HI1812V101R-10  [L1812]
BD8  HI1812V101R-10  [L1812]
C119  10uF/6.3V  [C0402]
C120  4.7uF/6.3V  [C0402]
C121  0.1uF  [C0402]
C122  0.1uF  [C0402]
C123  10uF/6.3V  [C0402]
C124  4.7uF/6.3V  [C0402]
C125  0.1uF  [C0402]
C126  0.1uF  [C0402]
C127  10uF/6.3V  [C0402]
C128  4.7uF/6.3V  [C0402]
C129  0.1uF  [C0402]
C130  0.1uF  [C0402]
C131  10uF/6.3V  [C0402]
C132  4.7uF/6.3V  [C0402]
C133  0.1uF  [C0402]
C134  0.1uF  [C0402]
C135  10uF/6.3V  [C0402]
C136  4.7uF/6.3V  [C0402]
C137  0.1uF  [C0402]
C138  X_100uF6.3V  [C1206]
C139  X_100uF6.3V  [C1206]
C140  10uF/6.3V  [C0402]
C141  4.7uF/6.3V  [C0402]
C142  0.1uF  [C0402]
C143  0.1uF  [C0402]
C144  47uF6.3V  [C0805]
C145  47uF6.3V  [C0805]
C146  10uF/6.3V  [C0402]
C147  4.7uF/6.3V  [C0402]
C148  0.1uF  [C0402]
C149  0.1uF  [C0402]
C150  47uF6.3V  [C0805]
C151  10uF/6.3V  [C0402]
C152  4.7uF/6.3V  [C0402]
C153  0.1uF  [C0402]
C154  0.1uF  [C0402]
C155  47uF6.3V  [C0805]
C156  10uF/6.3V  [C0402]
C157  4.7uF/6.3V  [C0402]
C158  0.1uF  [C0402]
C159  0.1uF  [C0402]
C160  10uF/6.3V  [C0402]
C161  4.7uF/6.3V  [C0402]
C162  0.1uF  [C0402]
C163  47uF6.3V  [C0805]
C164  10uF/6.3V  [C0402]
C165  4.7uF/6.3V  [C0402]
C166  0.1uF  [C0402]
C167  0.1uF  [C0402]
sheet 18_GPIO
U6  PI7C9X3G808GP  [HFCBGA_196_15X15]  (sections A,B,C,D,E)

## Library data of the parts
C36-C45 C52-C54 C100 C102-C104 C107-C111 C113-C118 C121 C125 C126 C129 C133 C134 C137-C139 C144 C145 C150 C155 = C_MLCC: CLASS: DISCRETE; Symbol Name: _
R25-R28 = R_2P: CLASS: DISCRETE
U4 U5 = AP7361C_0: CLASS: IC
C46-C51 C55-C58 C60 C62 C64 C65 C74-C77 C89-C92 = C_MLCC_0: Symbol Name: _
P2 = PCIex4
R29 R30 = R_2
R31-R33 R37 R38 R41-R43 R46 R48-R67 R69 R70 R72-R74 R79 RB2 RB4 = R_2P: Symbol Name: _
C66-C73 C78-C83 C85-C88 C93-C98 = C_MLCC: Symbol Name: _
R34-R36 R39 R40 R44 R45 = R_2P: Remark: _; Symbol Name: _
SLOT1 = PCIExp_x4_0
SLOT2-SLOT6 = PCIExp_x4_1
J1 = HEADER_3_1
SLOT7 = PCIe_x16_Conn_0.
C99 C101 C106 C119 C120 C123 C124 C127 C128 C131 C132 C135 C136 C140 C141 C146 C147 C151 C152 C156 C157 C160 C161 C164 C165 = C_MLCC_0: alt_symbols: (c0402,c0402_bga;b:c0402,c0402_bga)
C105 C112 = C_MLCC_0: Asm Cfg: 5010; Asm Comm: 5010; CLASS: DISCRETE; GREEN_TYPE: 1-RH§C¦Ã¬V; Symbol Name: _
DS6-DS14 = LED_0
J2 = CON2
J3 = BH1X4B-1_9: Symbol Name: _
R68 RD1 RD2 RD14-RD29 RD85 RP7-RP26 RP176 RP177 = R_2P
RD7-RD13 = R: Asm Cfg: 5010; Asm Comm: 5010; GREEN_TYPE: 7-HE µL³¿¯À&¼Ú·ù±Æ¥~±ø´Ú; Remark: _; Symbol Name: _
SW2 SW3 = SW_DIP-6
SW4 = SW_SMT-4_0
TP14 = TP_0
U7 = W25QXX_0
U8 = W25QXX_3
U9 = SN74AVC16T245
U10 = PI4ULS5V108LEX
BD1 BD3 BD4 BD6-BD8 = BEAD: Mod: _; New Description: ,IND FERRITE BEAD,110Ohm,25%,1206,5400mA,0.015Ohm; Old PN: _; Remark: _; Symbol Name: _
C122 C130 C142 C143 C148 C149 C153 C154 C158 C159 C162 C163 C166 C167 = C_MLCC: CLASS: DISCRETE; Symbol Name: _; alt_symbols: (c0402,c0402_bga;b:c0402,c0402_bga)
U6 = PI7C9X3G808GP_17

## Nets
0.95V_CVDDC: BD3.2 C38.2 C39.2 C40.2 R25.1 U4.1(OUT)
0.95V_VDDC: BD1.2 ; also on sheet 20
0.95V_VP: BD4.2 ; also on sheet 20
0.95VDDC: BD1.1 C119.2 C120.2 C121.2 C122.2 C123.2 C124.2 C125.2 C126.2 C127.2 C128.2 C129.2 C130.2 C131.2 C132.2 C133.2 C134.2 U6.F6(VDDC1) U6.F8(VDDC2) U6.G7(VDDC3) U6.G9(VDDC4) U6.H6(VDDC5) U6.H8(VDDC6) U6.J7(VDDC7) U6.J9(VDDC8)
0.95VP: BD4.1 C138.2 C139.2 C140.2 C141.2 C142.2 C143.2 C144.2 C145.2 C146.2 C147.2 C148.2 C149.2 U6.F10(VP1) U6.G5(VP2) U6.H10(VP3) U6.J5(VP4)
1.8V_EXT: BD6.2 BD7.2 BD8.2 C43.2 C44.2 C45.2 C99.2 C101.2 C102.2 C104.2 C106.2 C107.2 C108.2 C113.2 C114.2 C115.2 R27.1 R34.1 R35.1 R36.1 R39.1 R44.1 R50.2 R51.2 R52.2 R53.2 R54.2 R55.2 RP7.1 RP8.1 RP9.1 RP10.1 RP11.1 RP12.1 RP21.1 RP23.1 RP176.2 RP177.2 U5.1(OUT) U7.8(VCC) U8.2(VREF1) U9.7(VCCB1) U9.18(VCCB2) U10.2(VREFA) ; also on sheet 14 19
1.8VDDR: BD6.1 C150.2 C151.2 C152.2 C153.2 C154.2 C155.2 C156.2 C157.2 C158.2 C159.2 U6.D4(VDDR1) U6.D11(VDDR2) U6.L4(VDDR3) U6.L11(VDDR4)
1.8VPH: BD8.1 C163.2 C164.2 C165.2 C166.2 C167.2 U6.D8(VPH1) U6.L8(VPH2)
3.3V_EXT: C36.2 C37.2 C41.2 C42.2 C62.2 C64.2 C65.2 C77.2 C91.2 C92.2 C100.2 C103.2 C109.2 C110.2 C111.2 C116.2 C117.2 C118.2 R40.1 R45.1 R56.2 R57.2 R58.2 R61.2 R62.2 R63.2 R64.2 R65.2 R66.2 R67.2 R69.2 R70.1 R74.2 RP13.1 RP14.1 RP15.1 RP16.1 RP17.1 RP18.1 RP19.1 RP20.1 RP22.1 RP24.1 RP25.1 RP26.1 SLOT1.A9(+3.3V) SLOT1.A10(+3.3V) SLOT1.B8(+3.3V) SLOT1.B10(3.3Vaux) SLOT2.A9(+3.3V) SLOT2.A10(+3.3V) SLOT2.B8(+3.3V) SLOT2.B10(3.3Vaux) SLOT3.A9(+3.3V) SLOT3.A10(+3.3V) SLOT3.B8(+3.3V) SLOT3.B10(3.3Vaux) SLOT5.A9(+3.3V) SLOT5.A10(+3.3V) SLOT5.B8(+3.3V) SLOT5.B10(3.3Vaux) SLOT6.A9(+3.3V) SLOT6.A10(+3.3V) SLOT6.B8(+3.3V) SLOT6.B10(3.3Vaux) SLOT7.A9(+3.3V2) SLOT7.A10(+3.3V3) SLOT7.B8(+3.3V1) SLOT7.B10(+3.3VAUX) U4.5(EN) U4.8(IN) U5.5(EN) U5.8(IN) U9.31(VCCA2) U9.42(VCCA3) ; also on sheet 13 15 19 20
3.3V_SL4_SHP: C76.2 SLOT4.A9(+3.3V) SLOT4.A10(+3.3V) SLOT4.B8(+3.3V) SLOT4.B10(3.3Vaux) ; also on sheet 19
3.3VAUX: C52.2 C53.2 C54.2 P2.B10(3.3Vaux)
12V_SL4_SHP: C75.2 SLOT4.A2(+12V) SLOT4.A3(+12V) SLOT4.B1(+12V) SLOT4.B2(+12V) SLOT4.B3(+12V) ; also on sheet 19
12VCC_EXT: C57.2 C58.2 C60.2 C74.2 C89.2 C90.2 SLOT1.A2(+12V) SLOT1.A3(+12V) SLOT1.B1(+12V) SLOT1.B2(+12V) SLOT1.B3(+12V) SLOT2.A2(+12V) SLOT2.A3(+12V) SLOT2.B1(+12V) SLOT2.B2(+12V) SLOT2.B3(+12V) SLOT3.A2(+12V) SLOT3.A3(+12V) SLOT3.B1(+12V) SLOT3.B2(+12V) SLOT3.B3(+12V) SLOT5.A2(+12V) SLOT5.A3(+12V) SLOT5.B1(+12V) SLOT5.B2(+12V) SLOT5.B3(+12V) SLOT6.A2(+12V) SLOT6.A3(+12V) SLOT6.B1(+12V) SLOT6.B2(+12V) SLOT6.B3(+12V) SLOT7.A2(+12V4) SLOT7.A3(+12V5) SLOT7.B1(+12V1) SLOT7.B2(+12V2) SLOT7.B3(+12V3) ; also on sheet 19 20
GND: C36.1 C37.1 C38.1 C39.1 C40.1 C41.1 C42.1 C43.1 C44.1 C45.1 C52.1 C53.1 C54.1 C57.1 C58.1 C60.1 C62.1 C64.1 C65.1 C74.1 C75.1 C76.1 C77.1 C89.1 C90.1 C91.1 C92.1 C99.1 C100.1 C101.1 C102.1 C103.1 C104.1 C105.1 C106.1 C107.1 C108.1 C109.1 C110.1 C111.1 C112.1 C113.1 C114.1 C115.1 C116.1 C117.1 C118.1 C119.1 C120.1 C121.1 C122.1 C123.1 C124.1 C125.1 C126.1 C127.1 C128.1 C129.1 C130.1 C131.1 C132.1 C133.1 C134.1 C135.1 C136.1 C137.1 C138.1 C139.1 C140.1 C141.1 C142.1 C143.1 C144.1 C145.1 C146.1 C147.1 C148.1 C149.1 C150.1 C151.1 C152.1 C153.1 C154.1 C155.1 C156.1 C157.1 C158.1 C159.1 C160.1 C161.1 C162.1 C163.1 C164.1 C165.1 C166.1 C167.1 J3.3 P2.A4(GND12) P2.A12(GND13) P2.A15(GND14) P2.A18(GND15) P2.A20(GND16) P2.A23(GND17) P2.A24(GND18) P2.A27(GND19) P2.A28(GND20) P2.A31(GND21) P2.B4(GND1) P2.B7(GND2) P2.B13(GND3) P2.B16(GND4) P2.B18(GND5) P2.B21(GND6) P2.B22(GND7) P2.B25(GND8) P2.B26(GND9) P2.B29(GND10) P2.B32(GND11) R26.2 R28.2 R59.1 R60.1 R72.2 R79.2 RD1.1 RD2.1 RD7.1 RD8.1 RD9.1 RD10.1 RD11.1 RD12.1 RD13.1 RD14.2 RD15.2 RD16.2 RD17.2 RD18.2 RD19.2 RD20.2 RD21.2 RD22.2 RD23.2 RD24.2 RD25.2 RD26.2 RD27.2 RD28.2 RD29.2 RD85.2 SLOT1.A1(PRSNT1#) SLOT1.A4(GND) SLOT1.A12(GND) SLOT1.A15(GND) SLOT1.A18(GND) SLOT1.A20(GND) SLOT1.A23(GND) SLOT1.A24(GND) SLOT1.A27(GND) SLOT1.A28(GND) SLOT1.A31(GND) SLOT1.B4(GND) SLOT1.B7(GND) SLOT1.B13(GND) SLOT1.B16(GND) SLOT1.B18(GND) SLOT1.B21(GND) SLOT1.B22(GND) SLOT1.B25(GND) SLOT1.B26(GND) SLOT1.B29(GND) SLOT1.B32(GND) SLOT2.A1(PRSNT1#) SLOT2.A4(GND) SLOT2.A12(GND) SLOT2.A15(GND) SLOT2.A18(GND) SLOT2.A20(GND) SLOT2.A23(GND) SLOT2.A24(GND) SLOT2.A27(GND) SLOT2.A28(GND) SLOT2.A31(GND) SLOT2.B4(GND) SLOT2.B7(GND) SLOT2.B13(GND) SLOT2.B16(GND) SLOT2.B18(GND) SLOT2.B21(GND) SLOT2.B22(GND) SLOT2.B25(GND) SLOT2.B26(GND) SLOT2.B29(GND) SLOT2.B32(GND) SLOT3.A1(PRSNT1#) SLOT3.A4(GND) SLOT3.A12(GND) SLOT3.A15(GND) SLOT3.A18(GND) SLOT3.A20(GND) SLOT3.A23(GND) SLOT3.A24(GND) SLOT3.A27(GND) SLOT3.A28(GND) SLOT3.A31(GND) SLOT3.B4(GND) SLOT3.B7(GND) SLOT3.B13(GND) SLOT3.B16(GND) SLOT3.B18(GND) SLOT3.B21(GND) SLOT3.B22(GND) SLOT3.B25(GND) SLOT3.B26(GND) SLOT3.B29(GND) SLOT3.B32(GND) SLOT4.A1(PRSNT1#) SLOT4.A4(GND) SLOT4.A12(GND) SLOT4.A15(GND) SLOT4.A18(GND) SLOT4.A20(GND) SLOT4.A23(GND) SLOT4.A24(GND) SLOT4.A27(GND) SLOT4.A28(GND) SLOT4.A31(GND) SLOT4.B4(GND) SLOT4.B7(GND) SLOT4.B13(GND) SLOT4.B16(GND) SLOT4.B18(GND) SLOT4.B21(GND) SLOT4.B22(GND) SLOT4.B25(GND) SLOT4.B26(GND) SLOT4.B29(GND) SLOT4.B32(GND) SLOT5.A1(PRSNT1#) SLOT5.A4(GND) SLOT5.A12(GND) SLOT5.A15(GND) SLOT5.A18(GND) SLOT5.A20(GND) SLOT5.A23(GND) SLOT5.A24(GND) SLOT5.A27(GND) SLOT5.A28(GND) SLOT5.A31(GND) SLOT5.B4(GND) SLOT5.B7(GND) SLOT5.B13(GND) SLOT5.B16(GND) SLOT5.B18(GND) SLOT5.B21(GND) SLOT5.B22(GND) SLOT5.B25(GND) SLOT5.B26(GND) SLOT5.B29(GND) SLOT5.B32(GND) SLOT6.A1(PRSNT1#) SLOT6.A4(GND) SLOT6.A12(GND) SLOT6.A15(GND) SLOT6.A18(GND) SLOT6.A20(GND) SLOT6.A23(GND) SLOT6.A24(GND) SLOT6.A27(GND) SLOT6.A28(GND) SLOT6.A31(GND) SLOT6.B4(GND) SLOT6.B7(GND) SLOT6.B13(GND) SLOT6.B16(GND) SLOT6.B18(GND) SLOT6.B21(GND) SLOT6.B22(GND) SLOT6.B25(GND) SLOT6.B26(GND) SLOT6.B29(GND) SLOT6.B32(GND) SLOT7.A1(PRSNT1_B) SLOT7.A4(GND35) SLOT7.A12(GND36) SLOT7.A15(GND37) SLOT7.A18(GND38) SLOT7.A20(GND39) SLOT7.A23(GND40) SLOT7.A24(GND41) SLOT7.A27(GND42) SLOT7.A28(GND43) SLOT7.A31(GND44) SLOT7.A34(GND45) SLOT7.A37(GND46) SLOT7.A38(GND47) SLOT7.A41(GND48) SLOT7.A42(GND49) SLOT7.A45(GND50) SLOT7.A46(GND51) SLOT7.A49(GND52) SLOT7.A51(GND53) SLOT7.A54(GND54) SLOT7.A55(GND55) SLOT7.A58(GND56) SLOT7.A59(GND57) SLOT7.A62(GND58) SLOT7.A63(GND59) SLOT7.A66(GND60) SLOT7.A67(GND61) SLOT7.A70(GND62) SLOT7.A71(GND63) SLOT7.A74(GND64) SLOT7.A75(GND65) SLOT7.A78(GND66) SLOT7.A79(GND67) SLOT7.A82(GND68) SLOT7.B4(GND1) SLOT7.B7(GND2) SLOT7.B13(GND3) SLOT7.B16(GND4) SLOT7.B18(GND5) SLOT7.B21(GND6) SLOT7.B22(GND7) SLOT7.B25(GND8) SLOT7.B26(GND9) SLOT7.B29(GND10) SLOT7.B32(GND11) SLOT7.B35(GND12) SLOT7.B36(GND13) SLOT7.B39(GND14) SLOT7.B40(GND15) SLOT7.B43(GND16) SLOT7.B44(GND17) SLOT7.B47(GND18) SLOT7.B49(GND19) SLOT7.B52(GND20) SLOT7.B53(GND21) SLOT7.B56(GND22) SLOT7.B57(GND23) SLOT7.B60(GND24) SLOT7.B61(GND25) SLOT7.B64(GND26) SLOT7.B65(GND27) SLOT7.B68(GND28) SLOT7.B69(GND29) SLOT7.B72(GND30) SLOT7.B73(GND31) SLOT7.B76(GND32) SLOT7.B77(GND33) SLOT7.B80(GND34) U4.4(GND) U4.9(GNDPAD) U5.4(GND) U5.9(GNDPAD) U6.A11(VSS1) U6.B2(VSS2) U6.B5(VSS3) U6.B11(VSS4) U6.C6(VSS5) U6.C7(VSS6) U6.C8(VSS7) U6.C9(VSS8) U6.C10(VSS9) U6.C13(VSS10) U6.D5(VSS11) U6.E2(VSS12) U6.E11(VSS13) U6.F5(VSS14) U6.F7(VSS15) U6.F9(VSS16) U6.F13(VSS17) U6.G6(VSS18) U6.G8(VSS19) U6.G10(VSS20) U6.H2(VSS21) U6.H5(VSS22) U6.H7(VSS23) U6.H9(VSS24) U6.J6(VSS25) U6.J8(VSS26) U6.J10(VSS27) U6.J13(VSS28) U6.K5(VSS29) U6.K11(VSS30) U6.L2(VSS31) U6.L5(VSS32) U6.M6(VSS33) U6.M7(VSS34) U6.M8(VSS35) U6.M9(VSS36) U6.M10(VSS37) U6.M13(VSS38) U6.N5(VSS39) U6.N11(VSS40) U6.P2(VSS41) U6.P5(VSS42) U6.P11(VSS43) U7.4(GND) U8.1(GND) U9.4(GND1) U9.10(GND2) U9.15(GND3) U9.21(GND4) U9.28(GND5) U9.34(GND6) U9.39(GND7) U9.45(GND8) U10.1(GND) ; also on sheet 13 14 15 19 20
0.95C_VDDC: BD3.1 C135.2 C136.2 C137.2 U6.E5(C_VDDC)
1.8C_VDDR: BD7.1 C160.2 C161.2 C162.2 U6.A5(C_VDDR)
CHIP_MODE0: RD2.2 U6.F11(CHIPMODE_0)
CHIP_MODE1: RD1.2 U6.G11(CHIPMODE_1)
CLKBUFPD_L: RP14.2 SW3.2(A2) U9.32(2A4)
CPERST_L: P2.A11(PERST#) ; also on sheet 15
CREFCLKN: P2.A14(REFCLK-) RB4.2
CREFCLKP: P2.A13(REFCLK+) RB2.2
Debug_mode_EN_[L]: R68.2 RP13.2 SW3.1(A1) U9.33(2A3)
Debug_mode_EN_L: R46.2 U9.16(2B3)
EECK: R46.1 U6.K13(EECK) U7.6(SCK)
EECS_L: R52.1 R59.2 U6.K14(EECS_L) U7.1(\\~{C}S)
EEDI: U6.K12(EEDI) U7.5(SI)
EEDO: R51.1 U6.J14(EEDO) U7.2(SO)
FATAL_ERR_L: R49.1 U9.14(2B2)
FATAL_ERR_L_LED: DS14.1(CATHODE) U9.35(2A2)
GPIO_26: U9.17(2B4) ; also on sheet 16
GPIO_30: U9.19(2B5) ; also on sheet 16
GPIO_31: U9.20(2B6) ; also on sheet 16
HOLD#: J2.1 R53.1 U7.7(\\~{HOL}D)
HOT_PLUG_EN_[L]: RP17.2 SW3.5(A5) U9.27(2A7)
HOT_PLUG_EN_L: R49.2 U6.G4(FATAL_ERR_L/HOT_PLUG_EN_L) U9.22(2B7)
HP_RST_7_L: R43.2 ; also on sheet 19
I2C_ADDR0: RP10.2 SW2.4(A4) U6.L12(I2C_ADDR0)
I2C_ADDR1: RP11.2 SW2.5(A5) U6.M14(I2C_ADDR1)
I2C_ADDR2: RP12.2 SW2.6(A6) U6.M12(I2C_ADDR2)
INTA_L: R48.1 TP14.1
JTAG_SEL_L: RP176.1 U6.A14(JTAG_SEL_L)
PDC_L_0: RD13.2 U6.P13(PDC_0_L)
PDC_L_1: R34.2 RD12.2 SLOT1.B17(PRSNT2#_X1) SLOT1.B31(PRSNT2#_X4) U6.P14(PDC_1_L)
PDC_L_2: R35.2 RD11.2 SLOT2.B17(PRSNT2#_X1) SLOT2.B31(PRSNT2#_X4) U6.P12(PDC_2_L)
PDC_L_3: R36.2 RD10.2 SLOT3.B17(PRSNT2#_X1) SLOT3.B31(PRSNT2#_X4) U6.N14(PDC_3_L)
PDC_L_4: RD9.2 U6.N13(PDC_4_L)
PDC_L_5: R39.2 RD8.2 SLOT5.B17(PRSNT2#_X1) SLOT5.B31(PRSNT2#_X4) U6.N12(PDC_5_L)
PDC_L_6: R44.2 RD7.2 SLOT6.B17(PRSNT2#_X1) SLOT6.B31(PRSNT2#_X4) U6.M11(PDC_6_L)
PDC_L_7: U6.N4(PDC_7_L) ; also on sheet 19
PERn0_RECEPT: P2.B15(PETn0) U6.A10(PERN00)
PERn1_RECEPT: U6.A9(PERN01) ; also on sheet 13
PERn2_RECEPT: U6.A7(PERN02) ; also on sheet 13
PERn3_RECEPT: U6.A6(PERN03) ; also on sheet 13
PERn4_RECEPT: SLOT4.A17(PERn0) U6.P6(PERN04)
PERn5_RECEPT: U6.P7(PERN05) ; also on sheet 13
PERn6_RECEPT: U6.P9(PERN06) ; also on sheet 13
PERn7_RECEPT: U6.P10(PERN07) ; also on sheet 13
PERp0_RECEPT: P2.B14(PETp0) U6.B10(PERP00)
PERp1_RECEPT: U6.B9(PERP01) ; also on sheet 13
PERp2_RECEPT: U6.B7(PERP02) ; also on sheet 13
PERp3_RECEPT: U6.B6(PERP03) ; also on sheet 13
PERp4_RECEPT: SLOT4.A16(PERp0) U6.N6(PERP04)
PERp5_RECEPT: U6.N7(PERP05) ; also on sheet 13
PERp6_RECEPT: U6.N9(PERP06) ; also on sheet 13
PERp7_RECEPT: U6.N10(PERP07) ; also on sheet 13
PERST#_SL1: R31.2 ; also on sheet 15
PERST#_SL2: R32.2 ; also on sheet 15
PERST#_SL3: R33.2 ; also on sheet 15
PERST#_SL4: R37.2 ; also on sheet 19
PERST#_SL5: R38.2 ; also on sheet 15
PERST#_SL6: R42.2 ; also on sheet 15
PERST#_SL7: R41.2 ; also on sheet 15
PERST_CHIP_L: RP23.2 U6.D13(PERST_L) U10.9(A7)
PERST_L: R73.2 ; also on sheet 15
PERST_L_3V3: RP24.2 U10.12(B7) ; also on sheet 15
PETn0_P0: C47.2 P2.A17(PERn0)
PETn0_RECEPT: C47.1 U6.D10(PETN00)
PETn1_P0: C49.2 P2.A22(PERn1)
PETn1_RECEPT: U6.D9(PETN01) ; also on sheet 13
PETn2_P0: C51.2 P2.A26(PERn2)
PETn2_RECEPT: U6.D7(PETN02) ; also on sheet 13
PETn3_P0: C56.2 P2.A30(PERn3)
PETn3_RECEPT: U6.D6(PETN03) ; also on sheet 13
PETn4_RECEPT: C79.2 U6.L6(PETN04)
PETn5_RECEPT: U6.L7(PETN05) ; also on sheet 13
PETn6_RECEPT: U6.L9(PETN06) ; also on sheet 13
PETn7_RECEPT: U6.L10(PETN07) ; also on sheet 13
PETp0_P0: C46.2 P2.A16(PERp0)
PETp0_RECEPT: C46.1 U6.E10(PETP00)
PETp1_P0: C48.2 P2.A21(PERp1)
PETp1_RECEPT: U6.E9(PETP01) ; also on sheet 13
PETp2_P0: C50.2 P2.A25(PERp2)
PETp2_RECEPT: U6.E7(PETP02) ; also on sheet 13
PETp3_P0: C55.2 P2.A29(PERp3)
PETp3_RECEPT: U6.E6(PETP03) ; also on sheet 13
PETp4_RECEPT: C78.2 U6.K6(PETP04)
PETp5_RECEPT: U6.K7(PETP05) ; also on sheet 13
PETp6_RECEPT: U6.K9(PETP06) ; also on sheet 13
PETp7_RECEPT: U6.K10(PETP07) ; also on sheet 13
PHY_SRAM_BYPASS: RP15.2 SW3.3(A3) U9.30(2A5)
PM_L11_EN_[L]: RP18.2 SW3.6(A6) U9.26(2A8)
PM_L11_EN_L: R48.2 U6.H4(INTA_L/PM_L11_EN_L) U9.23(2B8)
PORTCFG[0]: RP7.2 SW2.1(A1) U6.B12(PORTCFG_0)
PORTCFG[1]: RP8.2 SW2.2(A2) U6.C11(PORTCFG_1)
PORTCFG[2]: RP9.2 SW2.3(A3) U6.D12(PORTCFG_2)
PORTGOOD_L[0]: U6.E13(PORTGOOD_L_0) U9.2(1B1)
PORTGOOD_L[0]_LED: DS6.1(CATHODE) U9.47(1A1)
PORTGOOD_L[1]: U6.E14(PORTGOOD_L_1) U9.3(1B2)
PORTGOOD_L[1]_LED: DS7.1(CATHODE) U9.46(1A2)
PORTGOOD_L[2]: U6.F14(PORTGOOD_L_2) U9.5(1B3)
PORTGOOD_L[2]_LED: DS8.1(CATHODE) U9.44(1A3)
PORTGOOD_L[3]: U6.F12(PORTGOOD_L_3) U9.6(1B4)
PORTGOOD_L[3]_LED: DS9.1(CATHODE) U9.43(1A4)
PORTGOOD_L[4]: U6.G14(PORTGOOD_L_4) U9.8(1B5)
PORTGOOD_L[4]_LED: DS10.1(CATHODE) U9.41(1A5)
PORTGOOD_L[5]: U6.G12(PORTGOOD_L_5) U9.9(1B6)
PORTGOOD_L[5]_LED: DS11.1(CATHODE) U9.40(1A6)
PORTGOOD_L[6]: U6.G13(PORTGOOD_L_6) U9.11(1B7)
PORTGOOD_L[6]_LED: DS12.1(CATHODE) U9.38(1A7)
PORTGOOD_L[7]: U6.H14(PORTGOOD_L_7) U9.12(1B8)
PORTGOOD_L[7]_LED: DS13.1(CATHODE) U9.37(1A8)
PRSNT#: P2.A1(PRSNT1#) P2.B17(PRSNT2#_1) P2.B31(PRSNT2#_4)
PRSNT#_SL4: R40.2 SLOT4.B17(PRSNT2#_X1) SLOT4.B31(PRSNT2#_X4) ; also on sheet 19
PRSNT#_SL7: R45.2 SLOT7.B17(PRSNT2_x1_B) SLOT7.B31(PRSNT2_x4_B) SLOT7.B48(PRSNT2_x8_B) SLOT7.B81(PRSNT2_x16_B) ; also on sheet 19
REFCLKIN_R: RB4.1 ; also on sheet 14
REFCLKIP_R: RB2.1 ; also on sheet 14
REFCLKN_SL1: SLOT1.A14(REFCLK-) ; also on sheet 14
REFCLKN_SL2: SLOT2.A14(REFCLK-) ; also on sheet 14
REFCLKN_SL3: SLOT3.A14(REFCLK-) ; also on sheet 14
REFCLKN_SL4: SLOT4.A14(REFCLK-) ; also on sheet 14
REFCLKN_SL5: SLOT5.A14(REFCLK-) ; also on sheet 14
REFCLKN_SL6: SLOT6.A14(REFCLK-) ; also on sheet 14
REFCLKN_SL7: SLOT7.A14(REFCLK_N) ; also on sheet 14
REFCLKP_SL1: SLOT1.A13(REFCLK+) ; also on sheet 14
REFCLKP_SL2: SLOT2.A13(REFCLK+) ; also on sheet 14
REFCLKP_SL3: SLOT3.A13(REFCLK+) ; also on sheet 14
REFCLKP_SL4: SLOT4.A13(REFCLK+) ; also on sheet 14
REFCLKP_SL5: SLOT5.A13(REFCLK+) ; also on sheet 14
REFCLKP_SL6: SLOT6.A13(REFCLK+) ; also on sheet 14
REFCLKP_SL7: SLOT7.A13(REFCLK_P) ; also on sheet 14
RST#_SL1: R31.1 SLOT1.A11(PERST#)
RST#_SL2: R32.1 SLOT2.A11(PERST#)
RST#_SL3: R33.1 SLOT3.A11(PERST#)
RST#_SL4: R37.1 SLOT4.A11(PERST#)
RST#_SL5: R38.1 SLOT5.A11(PERST#)
RST#_SL6: R42.1 SLOT6.A11(PERST#)
RST#_SL7: J1.2 SLOT7.A11(PERST_B)
RXn1_SL1: SLOT1.A17(PERn0) ; also on sheet 13
RXn1_UP: P2.B20(PETn1) ; also on sheet 13
RXn2_SL2: SLOT2.A17(PERn0) ; also on sheet 13
RXn2_UP: P2.B24(PETn2) ; also on sheet 13
RXn3_SL2: SLOT2.A22(PERn1) ; also on sheet 13
RXn3_SL3: SLOT3.A17(PERn0) ; also on sheet 13
RXn3_UP: P2.B28(PETn3) ; also on sheet 13
RXn5_SL4: SLOT4.A22(PERn1) ; also on sheet 13
RXn5_SL5: SLOT5.A17(PERn0) ; also on sheet 13
RXn6_SL4: SLOT4.A26(PERn2) ; also on sheet 13
RXn6_SL6: SLOT6.A17(PERn0) ; also on sheet 13
RXn7_SL4: SLOT4.A30(PERn3) ; also on sheet 13
RXn7_SL6: SLOT6.A22(PERn1) ; also on sheet 13
RXn7_SL7: SLOT7.A17(PERn0) ; also on sheet 13
RXp1_SL1: SLOT1.A16(PERp0) ; also on sheet 13
RXp1_UP: P2.B19(PETp1) ; also on sheet 13
RXp2_SL2: SLOT2.A16(PERp0) ; also on sheet 13
RXp2_UP: P2.B23(PETp2) ; also on sheet 13
RXp3_SL2: SLOT2.A21(PERp1) ; also on sheet 13
RXp3_SL3: SLOT3.A16(PERp0) ; also on sheet 13
RXp3_UP: P2.B27(PETp3) ; also on sheet 13
RXp5_SL4: SLOT4.A21(PERp1) ; also on sheet 13
RXp5_SL5: SLOT5.A16(PERp0) ; also on sheet 13
RXp6_SL4: SLOT4.A25(PERp2) ; also on sheet 13
RXp6_SL6: SLOT6.A16(PERp0) ; also on sheet 13
RXp7_SL4: SLOT4.A29(PERp3) ; also on sheet 13
RXp7_SL6: SLOT6.A21(PERp1) ; also on sheet 13
RXp7_SL7: SLOT7.A16(PERp0) ; also on sheet 13
SCL_I2C: R55.1 U6.L14(SCL_I2C) U8.3(SCL1)
SCL_I2C_CN: J3.1 R29.1 R57.1 U8.6(SCL2)
SDA_I2C: R54.1 U6.L13(SDA_I2C) U8.4(SDA1)
SDA_I2C_CN: J3.2 R30.1 R58.1 U8.5(SDA2)
SHCL_I2C: U6.P4(SHCL_I2C) ; also on sheet 19
SHDA_I2C: U6.P3(SHDA_I2C) ; also on sheet 19
SHPCINT_L: RP21.2 U6.P1(SHPCINT_L) U10.10(A8)
SHPINT: RP25.2 U10.11(B8) ; also on sheet 19
SMBCLK_P0: P2.B5(SMCLK) R29.2
SMBDATA_P0: P2.B6(SMDAT) R30.2
SMBUS_EN_L: RP177.1 U6.K8(SMBUS_EN_L)
SURPRISE_HP_EN: RP16.2 SW3.4(A4) U9.29(2A6)
TMS: R79.1 U6.H12(TMS)
TRST_L: R72.1 U6.H11(TRST_L)
TXn1_S1: C69.1 SLOT1.B15(PETn0)
TXn1_SL1: C69.2 ; also on sheet 13
TXn1_UP: C49.1 ; also on sheet 13
TXn2_S2: C70.1 SLOT2.B15(PETn0)
TXn2_SL2: C70.2 ; also on sheet 13
TXn2_UP: C51.1 ; also on sheet 13
TXn3_S2: C73.1 SLOT2.B20(PETn1)
TXn3_S3: C71.1 SLOT3.B15(PETn0)
TXn3_SL2: C73.2 ; also on sheet 13
TXn3_SL3: C71.2 ; also on sheet 13
TXn3_UP: C56.1 ; also on sheet 13
TXn4_S4: C79.1 SLOT4.B15(PETn0)
TXn5_S4: C83.1 SLOT4.B20(PETn1)
TXn5_S5: C81.1 SLOT5.B15(PETn0)
TXn5_SL4: C83.2 ; also on sheet 13
TXn5_SL5: C81.2 ; also on sheet 13
TXn6_S4: C86.1 SLOT4.B24(PETn2)
TXn6_S6: C94.1 SLOT6.B15(PETn0)
TXn6_SL4: C86.2 ; also on sheet 13
TXn6_SL6: C94.2 ; also on sheet 13
TXn7_S4: C88.1 SLOT4.B28(PETn3)
TXn7_S6: C98.1 SLOT6.B20(PETn1)
TXn7_S7: C96.1 SLOT7.B15(PETn0)
TXn7_SL4: C88.2 ; also on sheet 13
TXn7_SL6: C98.2 ; also on sheet 13
TXn7_SL7: C96.2 ; also on sheet 13
TXp1_S1: C66.1 SLOT1.B14(PETp0)
TXp1_SL1: C66.2 ; also on sheet 13
TXp1_UP: C48.1 ; also on sheet 13
TXp2_S2: C67.1 SLOT2.B14(PETp0)
TXp2_SL2: C67.2 ; also on sheet 13
TXp2_UP: C50.1 ; also on sheet 13
TXp3_S2: C72.1 SLOT2.B19(PETp1)
TXp3_S3: C68.1 SLOT3.B14(PETp0)
TXp3_SL2: C72.2 ; also on sheet 13
TXp3_SL3: C68.2 ; also on sheet 13
TXp3_UP: C55.1 ; also on sheet 13
TXp4_S4: C78.1 SLOT4.B14(PETp0)
TXp5_S4: C82.1 SLOT4.B19(PETp1)
TXp5_S5: C80.1 SLOT5.B14(PETp0)
TXp5_SL4: C82.2 ; also on sheet 13
TXp5_SL5: C80.2 ; also on sheet 13
TXp6_S4: C85.1 SLOT4.B23(PETp2)
TXp6_S6: C93.1 SLOT6.B14(PETp0)
TXp6_SL4: C85.2 ; also on sheet 13
TXp6_SL6: C93.2 ; also on sheet 13
TXp7_S4: C87.1 SLOT4.B27(PETp3)
TXp7_S6: C97.1 SLOT6.B19(PETp1)
TXp7_S7: C95.1 SLOT7.B14(PETp0)
TXp7_SL4: C87.2 ; also on sheet 13
TXp7_SL6: C97.2 ; also on sheet 13
TXp7_SL7: C95.2 ; also on sheet 13
U9_1DIR: RP26.2 SW4.4(A4) U9.1(1DIR)
U9_1OE_L: RP19.2 SW4.2(A2) U9.48(\\~{1O}E)
U9_2DIR: RP20.2 SW4.3(A3) U9.24(2DIR)
U9_2OE_L: R73.1 RP22.2 SW4.1(A1) U9.25(\\~{2O}E)
U9_OE: R68.1 ; also on sheet 19
WP#: R50.1 U7.3(\\~{W}P)
N26082740: R25.2 R26.1 U4.3(ADJ)
N26090904: R27.2 R28.1 U5.3(ADJ)
N27551266: P2.A6(JTAG3-TDI) P2.A7(JTAG4-TDO)
N27777045: RD22.1 SW3.10(B3)
N27777049: RD23.1 SW3.9(B4)
N27777059: RD24.1 SW3.8(B5)
N27777063: RD25.1 SW3.7(B6)
N27777100: RD20.1 SW3.12(B1)
N27777106: RD21.1 SW3.11(B2)
N27777288: DS6.2(ANODE) R61.1
N27777297: DS7.2(ANODE) R62.1
N27777306: DS8.2(ANODE) R63.1
N27777315: DS9.2(ANODE) R64.1
N27777324: DS10.2(ANODE) R65.1
N27777333: DS11.2(ANODE) R66.1
N27777342: DS12.2(ANODE) R67.1
N27777351: DS13.2(ANODE) R69.1
N27779492: RD17.1 SW2.9(B4)
N27779498: RD14.1 SW2.12(B1)
N27779522: RD15.1 SW2.11(B2)
N27779528: RD16.1 SW2.10(B3)
N27779562: RD18.1 SW2.8(B5)
N27779566: RD19.1 SW2.7(B6)
N27788287: J2.2 R60.2
N27788814: C105.2 R56.1 U8.7(VREF2) U8.8(EN)
N27803637: J1.1 R41.1
N27803664: J1.3 R43.1
N27812988: RD26.1 SW4.8(B1)
N27813004: RD27.1 SW4.7(B2)
N27813020: RD28.1 SW4.6(B3)
N27813031: RD29.1 SW4.5(B4)
N27849923: C112.2 R74.1 U10.19(VREFB) U10.20(EN)
N27973277: DS14.2(ANODE) R70.2
N28339986: RD85.1 U6.J4(TEST)

Not connected (* = marked no-connect by the designer): P2 A2(+12V4)* A3(+12V5)* A5(JTAG2-TCK)* A8(JTAG5-TMS)* A9(+3.3V2)* A10(+3.3V3)* A19(RSVD3)* A32(RSVD4)* B1(+12V1)* B2(+12V2)* B3(+12V3)* B8(+3.3V1)* B9(JTAG1-TRST#)* B11(WAKE#)* B12(RSVD1)* B30(RSVD2)*; SLOT1 A5(TCK)* A6(TDI)* A7(TDO)* A8(TMS)* A19(RSVD3)* A21(PERp1)* A22(PERn1)* A25(PERp2)* A26(PERn2)* A29(PERp3)* A30(PERn3)* A32(RSVD4)* B5(SMCLK)* B6(SMDAT)* B9(TRST#)* B11(WAKE#)* B12(RSVD1)* B19(PETp1)* B20(PETn1)* B23(PETp2)* B24(PETn2)* B27(PETp3)* B28(PETn3)* B30(RSVD2)*; SLOT2 A5(TCK)* A6(TDI)* A7(TDO)* A8(TMS)* A19(RSVD3)* A25(PERp2)* A26(PERn2)* A29(PERp3)* A30(PERn3)* A32(RSVD4)* B5(SMCLK)* B6(SMDAT)* B9(TRST#)* B11(WAKE#)* B12(RSVD1)* B23(PETp2)* B24(PETn2)* B27(PETp3)* B28(PETn3)* B30(RSVD2)*; SLOT3 A5(TCK)* A6(TDI)* A7(TDO)* A8(TMS)* A19(RSVD3)* A21(PERp1)* A22(PERn1)* A25(PERp2)* A26(PERn2)* A29(PERp3)* A30(PERn3)* A32(RSVD4)* B5(SMCLK)* B6(SMDAT)* B9(TRST#)* B11(WAKE#)* B12(RSVD1)* B19(PETp1)* B20(PETn1)* B23(PETp2)* B24(PETn2)* B27(PETp3)* B28(PETn3)* B30(RSVD2)*; SLOT4 A5(TCK)* A6(TDI)* A7(TDO)* A8(TMS)* A19(RSVD3)* A32(RSVD4)* B5(SMCLK)* B6(SMDAT)* B9(TRST#)* B11(WAKE#)* B12(RSVD1)* B30(RSVD2)*; SLOT5 A5(TCK)* A6(TDI)* A7(TDO)* A8(TMS)* A19(RSVD3)* A21(PERp1)* A22(PERn1)* A25(PERp2)* A26(PERn2)* A29(PERp3)* A30(PERn3)* A32(RSVD4)* B5(SMCLK)* B6(SMDAT)* B9(TRST#)* B11(WAKE#)* B12(RSVD1)* B19(PETp1)* B20(PETn1)* B23(PETp2)* B24(PETn2)* B27(PETp3)* B28(PETn3)* B30(RSVD2)*; SLOT6 A5(TCK)* A6(TDI)* A7(TDO)* A8(TMS)* A19(RSVD3)* A25(PERp2)* A26(PERn2)* A29(PERp3)* A30(PERn3)* A32(RSVD4)* B5(SMCLK)* B6(SMDAT)* B9(TRST#)* B11(WAKE#)* B12(RSVD1)* B23(PETp2)* B24(PETn2)* B27(PETp3)* B28(PETn3)* B30(RSVD2)*; SLOT7 A5(JTAG2_-_TCK)* A6(JTAG3_-_TDI)* A7(JTAG4_-_TDO)* A8(JTAG5_-_TMS)* A19(RSVD4)* A21(PERp1)* A22(PERn1)* A25(PERp2)* A26(PERn2)* A29(PERp3)* A30(PERn3)* A32(RSVD5)* A33(RSVD6)* A35(PERp4)* A36(PERn4)* A39(PERp5)* A40(PERn5)* A43(PERp6)* A44(PERn6)* A47(PERp7)* A48(PERn7)* A50(RSVD7)* A52(PERp8)* A53(PERn8)* A56(PERp9)* A57(PERn9)* A60(PERp10)* A61(PERn10)* A64(PERp11)* A65(PERn11)* A68(PERp12)* A69(PERn12)* A72(PERp13)* A73(PERn13)* A76(PERp14)* A77(PERn14)* A80(PERp15)* A81(PERn15)* B5(SMCLK)* B6(SMDAT)* B9(JTAG1_-_TRST_B)* B11(WAKE_B)* B12(RSVD1)* B19(PETp1)* B20(PETn1)* B23(PETp2)* B24(PETn2)* B27(PETp3)* B28(PETn3)* B30(RSVD2)* B33(PETp4)* B34(PETn4)* B37(PETp5)* B38(PETn5)* B41(PETp6)* B42(PETn6)* B45(PETp7)* B46(PETn7)* B50(PETp8)* B51(PETn8)* B54(PETp9)* B55(PETn9)* B58(PETp10)* B59(PETn10)* B62(PETp11)* B63(PETn11)* B66(PETp12)* B67(PETn12)* B70(PETp13)* B71(PETn13)* B74(PETp14)* B75(PETn14)* B78(PETp15)* B79(PETn15)* B82(RSVD3)*; U4 2(NC1)* 6(NC2)* 7(NC3)*; U5 2(NC1)* 6(NC2)* 7(NC3)*; U6 H13(TDO)* J11(TCK)* J12(TDI)*; U9 13(2B1) 36(2A1); U10 3(A1)* 4(A2)* 5(A3)* 6(A4)* 7(A5)* 8(A6)* 13(B6)* 14(B5)* 15(B4)* 16(B3)* 17(B2)* 18(B1)*

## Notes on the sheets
sheet 1
- (0.95V / 1A)
- Vout=0.8V{(R1+R2)/R2}
- R1
- R2
- (1.8V / 1A)
- Vout=0.8V{(R1+R2)/R2}
- R1
- R2
sheet 2
- PI7C9X3G808GP  reference circuit
- Title
- Page
- 01_COVER SHEET
- 1
- Ver: 1.6
- 02_MECHANICAL BLOCK
- 2
- 03_POWER DELIVERY
- 3
- 04_REFCLK BLOCK
- 4
- Power
- 05_PORT-LANE MAPPING
- 5
- LMZ31520
- LMZ31704
- 06_ATX & 3.3V_EXT
- 6
- AP7361C-ADJ
- Packet Switch
- I/O Expander
- 07_3V3_to_1V8&0.95V_LDO
- 7
- PI7C9X3G808GP
- PI4IOE5V9555
- 08_UPSTREAM
- 8
- Dual Hot-Swap Power Controller
- 09_SLOT 1 - 3
- 9
- Bidirectional Level Shifter
- TPS2311
- 10_SLOT 4 - 7
- 10
- PI4ULS5V108LEX
- 11_PI7C9X3G808GP MODE SEL
- 11
- Busl Switch
- SPI Serial Flash Memory
- 12_PI7C9X3G808GP DIFF PAIR
- 12
- PI3B3257
- AT25XE011-SSHN-T
- 13_PI7C9X3G808GP POWER
- 13
- TTL GATE
- I2C Voltage-Level Translator
- 14_SIGNAL SWITCH
- 14
- 74HC08
- 74HC04
- PI6ULS5V9306UAE
- 15_CLOCK BUFFER
- 15
- Signal Switch
- 16_SHP / PARTIAL HP / PM L1.1
- 16
- PI3PCIE3212ZBEX
- PI3PCIE3413ZHE
- 17_PERST SIGNAL & PORT LED
- 17
- 18_GPIO
- 18
- 19_REVISION HISTORY
- 19
- 20_DISCLAIMER
- 20
sheet 3
- Ports - Lanes mapping
- Function Block
- MODE
- 2Port
- 3Port
- 4Port
- 5Port
- 8Port
- Lane 0
- P0
- P0
- P0
- P0
- P0
- Slot
   1
- Slot
   2
- Slot
   3
- Slot 4
  (SHP) / PM L1.1
- Slot
   5
- Slot
   6
- Slot 7
  Partial PHP
- Lane 1
- P0
- P0
- P0
- P0
- P1
- Lane 2
- P0
- P0
- P1
- P0
- P2
- Lane 3
- P0
- P0
- P1
- P0
- P3
- (Lane5)
- (Lane6)
- (Lane7)
- (Lane5)
- (Lane6)
- (Lane7)
- (Lane7)
- Lane 4
- P4
- P4
- P4
- P4
- P4
- (Lane4)
- (Lane1)
- (Lane2)
- (Lane3)
- (Lane3)
- Lane 5
- P4
- P4
- P4
- P5
- P5
- Lane 6
- P4
- P5
- P5
- P6
- P6
- Lane 7
- P4
- P5
- P5
- P7
- P7
- U14-Signal SW
- U15-Signal SW
- U17-Signal SW
- U12-Signal SW
- U13-Signal SW
- U16-Signal SW
- (Lane3)
- (Lane2)
- U6 - Packet SW
  PI7C9X3G808GP
- (Lane1)
- (Lane0)
- REFCLKI
- REFCLK[1:0]
- REFCLK OUTPUT TO SLOTS
- P2
  X4 Golden Finger
- CREFCLK
- U20 - Clock Buffer
  LMK00338
- REFCLKO[7:0]
- Power Map
- 12VCC_EXT
- U1
  LMZ31530
- 3.3V_EXT
- P6
- SLOT 1 - 7
- U4 / U5
  AP7361C-ADJFGE-7
- U2
  LMZ31704
- 0.95_VDDC
- 1.8V_EXT
- 0.95_CVDDV
- U6 - Packet SW
  PI7C9X3G808GP
- 5VCC_EXT
- U3
  LMZ31704
- 0.95_VP
- P1
- 12VCC_EXT
- 12VCC_EXT
sheet 4
- Power Map
- Slot1
- Slot2
- Slot3
- 3.3V_EXT
- 6-Pin ATX
  +12V Power Conn.
       PWR1
- U1
  LMZ31530
- System
- LDO
- LDO
- Slot4
- 0.95C_VDDC
- 1.8V_XXX
- U2
  LMZ31704
- 0.95V_VDDC
- 4-Pin ATX
  +5V / +12V
  Power Conn.
  P1
- 0.95V_VP
- U6 - Packet SW
  PI7C9X3G808GP
- U3
  LMZ31704
- Slot5
- Slot6
- Slot7
sheet 5
- REFCLK BLOCK
- PHY0 CLOCK
- SLOT1
- CKMode = 0
  Internal
  path
- SLOT2
- SLOT3
- PHY1 CLOCK
- CLOCK BUFFER
  OUTPUT
- SLOT4
- SLOT5
- SLOT6
- From Root Complex
- CLOCK BUFFER
  INPUT
- SLOT7
- PI7C9X3G808GP
- CKMODE
- Mode
- 0
- Base (Default)
- 1
- CDSR
- When CKMODE is 0, all 8 lanes (0 ~7) of SERDES are driven by one reference clock source.
  When CKMODE is 1, 8 lanes of SERDES are driven by two separate reference clock source via two pairs of reference clock inputs.
sheet 6
- Port-Lane  Mapping
- A. Set Functional Mode
- C. Ports - Lanes mapping for different mode
- PORTCFG[2:0]
- PORTCFG[2]
- PORTCFG[1]
- PORTCFG[0]
- Functional Mode
- MODE
- 2Port
- 3Port
- 4Port
- 5Port
- 8Port
- 0
- 0
- 1
- 2Port - 8Lane Configuration
- Lane 0
- P0
- P0
- P0
- P0
- P0
- 0
- 1
- 0
- 3Port - 8Lane Configuration
- 0
- 1
- 1
- 4Port - 8Lane Configuration
- Lane 1
- P0
- P0
- P0
- P0
- P1
- 1
- 0
- 0
- 5Port - 8Lane Configuration
- Lane 2
- P0
- P0
- P1
- P0
- P2
- 1
- 0
- 1
- 8Port - 16Lane Configuration
- Lane 3
- P0
- P0
- P1
- P0
- P3
- Chipmode[1:0]
- Lane 4
- P4
- P4
- P4
- P4
- P4
- Chipmode1
- Chipmode0
- Mode
- Lane 5
- P4
- P4
- P4
- P5
- P5
- 0
- 0
- Normal
- 0
- 1
- Reserved
- Lane 6
- P4
- P5
- P5
- P6
- P6
- 1
- 0
- Reserved
- Lane 7
- P4
- P5
- P5
- P7
- P7
- 1
- 1
- Reserved
- B. Set Signal Switch for different modes
- Lane
- MODE
- 208
- 308
- 408
- 508
- 808
- 1
- Ln1_SEL
- L
- L
- L
- L
- H
- 2
- Ln2_SEL
- L
- L
- H
- L
- H
- Ln3_SEL1
- H
- H
- L
- H
- H
- 3
- Ln3_SEL2
- H
- H
- H
- H
- L
- 5
- Ln5_SEL
- H
- H
- H
- L
- L
- 6
- Ln6_SEL
- H
- L
- L
- L
- L
- Ln7_SEL1
- H
- H
- H
- L
- L
- 7
- Ln7_SEL2
- H
- L
- L
- H
- H
sheet 7
- Lane0~3
- External SMBus
sheet 8
- Series Hot Plug / PM L1.1 - Port 4
  Function In All Port Configuration Mode
- SLOT 4
  ( P4 )
- SLOT5
  ( P5 )
- Partial PHP (no IO expander or CPLD is found) - Port 7
  Function In Port Configuration 508 / 808 Mode
- SLOT6
  ( P5 / P6 )
- SLOT 7
  ( P7 )
- 1 - 2 = Normal Operation ( Default )
  2 - 3 = Partial PHP
sheet 9
- SLOT1
  ( P0 )
- SLOT2
  ( P1 / P2 )
- SLOT3
  ( P3 )
sheet 10
- CHIP_MODE[1:0]
- Mode
- 00
- Normal
- 01
- Reserved
- 10
- Reserved
- 11
- Reserved
- SHCL_I2C / SHDA_I2C / SHPCINT_L pull-up if SHP funciton not implement
- PORTCFG[2]
- PORTCFG[1]
- PORTCFG[0]
- Functional Mode
- default
  setting
- 0
- 0
- 0
- Reserved
- 0
- 0
- 1
- 2Port - 8Lane Configuration
- 0
- 1
- 0
- 1
- 0
- 3Port - 8Lane Configuration
- 1
- 0
- 0
- 1
- 1
- 4Port - 8Lane Configuration
- 0
- 0
- 1
- 0
- 0
- 5Port - 8Lane Configuration
- 1
- 0
- 1
- 8Port - 8Lane Configuration
- 1
- 1
- 0
- Reserved
- 1
- 1
- 1
- Reserved
- Debug_mode_EN_[L]
  1: Normal Mode (Default)
  0: Debug Mode
- Short this connector to
  bypass the EEPROM
- default
  setting
- AT25XE011-SSHN-T
- I2C Level Shift
- 1
- 1
- 1
- 1
- 1
- 1
- RESET Latch
- HOT_PLUG_EN_[L]
- SURPRISE_HP_EN
- PM_L11_EN_[L]
- Functional Mode
- 0
- 1
- 1
- Partial PHP
- 0
- 0
- 1
- Serial Hot Plug
- Level Shift for PERST / SHP
- 1
- 1
- 0
- PM L1.1
- INTA_L "PM L1-1 mode"
  0:     PM L1-1 mode
- FATAL_ERR_L "HOT_PLUG_EN_L"
  0:    GPIO[31:0] Parallel hot-plug mode
- Input
- CONTROL INPUTS
- OUTPUT CIRCUITS
- OE#
- DIR
- A PORT
- B PORT
- OPERATION
- default
  setting
- 1
- L
- L
- Enable
- Hi-Z
- B-> A
- 0
- 1
- L
- H
- Hi-Z
- Enable
- A-> B
- 0
- H
- X
- Hi-Z
- Hi-Z
- Isolation
- The control pins are supplied by VCCA
- GPIO[26] "CKBUFPD_L"
  1: Enable CLK buffer
  0: Disable CLK buffer
- GPIO[30] "PHY_SRAM_BYPASS"
  1: Bypass SRAM (Default)
  0: Not bypass SRAM
- GPIO[31] "SURPRISE_HP_EN"
  1: Surprised Hot-Plug: LED Management / Partial PHP (no IO expander or CPLD is found)
  0: Managed Hot-Plug: PCIe SHP / PCIe PHP (no IO expander or CPLD is found)
sheet 11
- 208
- 308
- 408
- 508
- 808
- P0
- P0
- P1
- P0
- P0
- P0
- P1
- P2
- P3
- P4
- P4
- P4
- P4
- P5
- P5
- P4
- P5
- P5
- P6
- P6
- P7
- P7
